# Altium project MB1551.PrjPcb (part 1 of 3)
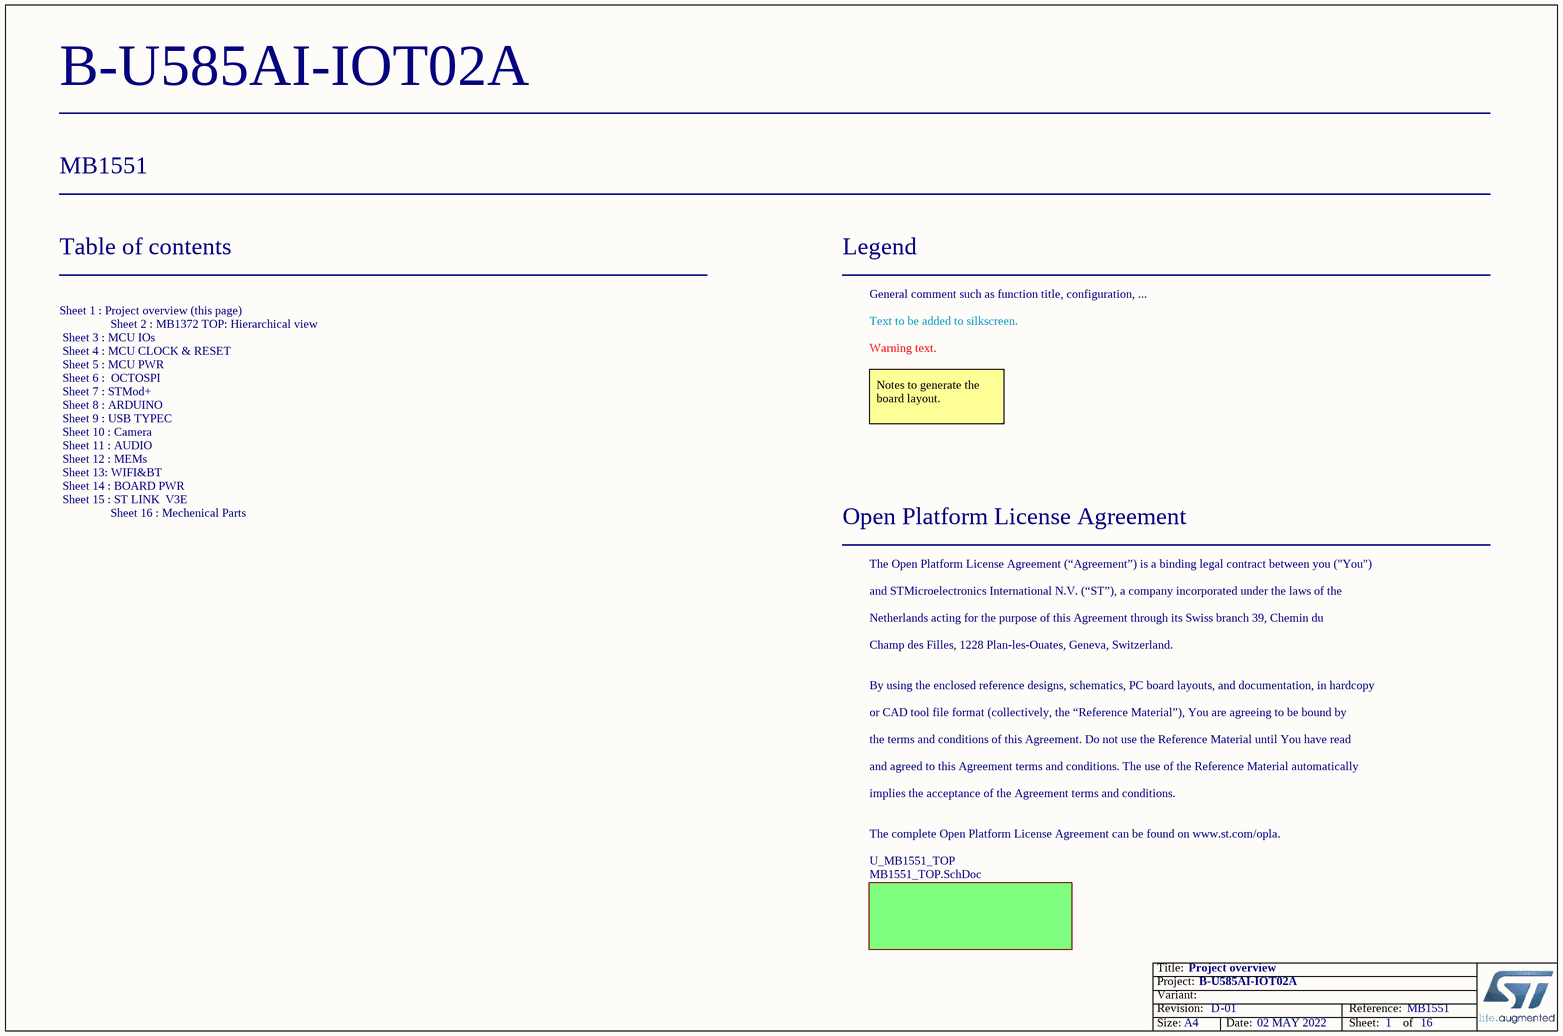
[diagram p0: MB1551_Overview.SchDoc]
Board_Reference: MB1551; Board_PCB_Revision: D; Board_Name: B-U585AI-IOT02A; Board_Document_Date: 02 MAY 2022; Board_Assembly_Revision: 01
16 sheets, 325 parts. Net scope: flat (ports and power ports of the same name join across sheets).
Board file: MB1551.PcbDoc
Sheets:
  MB1551_Overview.SchDoc
    U_MB1551_TOP = MB1551_TOP.SchDoc
      U_ARDUINO = ARDUINO.SchDoc
      U_AUDIO = AUDIO.SchDoc
      U_BOARD_PWR = BOARD_PWR.SchDoc
      U_Camera = Camera.SchDoc
      U_MCU_CLOCK_&_RESET = MCU_CLOCK_&_RESET.SchDoc
      U_MCU_IO = MCU_IO.SchDoc
      U_MCU_PWR = MCU_PWR.SchDoc
      U_Mechanical_Parts = Mechanical_Parts.SchDoc
      U_MEMs = MEMs.SchDoc
      U_OCTOSPI = OCTOSPI.SchDoc
      U_STMod+ = STMod+.SchDoc
      U_ST_LINK_V3E = ST_LINK_V3E.SchDoc
      U_WIFI&BT = WIFI&BT.SchDoc
      U_USB_TYPEC = USB_TYPEC.SchDoc

## Sheet MB1551_Overview.SchDoc: Project overview
size A4; Date: Not used; ApprovedBy: Not used; CheckedBy: Not used; Author: Not used; CompanyName: STMicroelectronics; DrawnBy: Not used; Engineer: Not used; Organization: Not used; Address1: Not used; Address2: Not used; Address3: Not used; Address4: Not used; DocumentNumber: 1; Revision: Not used; SheetNumber: 1; SheetTotal: 16

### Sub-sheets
U_MB1551_TOP = MB1551_TOP.SchDoc: no entries

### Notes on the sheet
- Table of contents
- Legend
- General comment such as function title, configuration, ...
- Text to be added to silkscreen.
- Warning text.
- Notes to generate the board layout.
- Open Platform License Agreement
- The Open Platform License Agreement (“Agreement”) is a binding legal contract between you ("You")
- Sheet 1 : Project overview (this page)
  Sheet 2 : MB1372 TOP: Hierarchical view
  Sheet 3 : MCU IOs
  Sheet 4 : MCU CLOCK & RESET
  Sheet 5 : MCU PWR
  Sheet 6 :  OCTOSPI
  Sheet 7 : STMod+
  Sheet 8 : ARDUINO
  Sheet 9 : USB TYPEC
  Sheet 10 : Camera
  Sheet 11 : AUDIO
  Sheet 12 : MEMs
  Sheet 13: WIFI&BT
  Sheet 14 : BOARD PWR
  Sheet 15 : ST LINK  V3E
  Sheet 16 : Mechenical Parts
- and STMicroelectronics International N.V. (“ST”), a company incorporated under the laws of the
- Netherlands acting for the purpose of this Agreement through its Swiss branch 39, Chemin du
- Champ des Filles, 1228 Plan-les-Ouates, Geneva, Switzerland.
- By using the enclosed reference designs, schematics, PC board layouts, and documentation, in hardcopy
- or CAD tool file format (collectively, the “Reference Material”), You are agreeing to be bound by
- the terms and conditions of this Agreement. Do not use the Reference Material until You have read
- and agreed to this Agreement terms and conditions. The use of the Reference Material automatically
- implies the acceptance of the Agreement terms and conditions.
- The complete Open Platform License Agreement can be found on www.st.com/opla.

## Sheet MB1551_TOP.SchDoc: TOP: Hierarchical view
size A3; Date: Not used; ApprovedBy: Not used; CheckedBy: Not used; Author: Not used; CompanyName: STMicroelectronics; DrawnBy: Not used; Engineer: Not used; Organization: Not used; Address1: Not used; Address2: Not used; Address3: Not used; Address4: Not used; DocumentNumber: 2; Revision: Not used; SheetNumber: 2; SheetTotal: 16
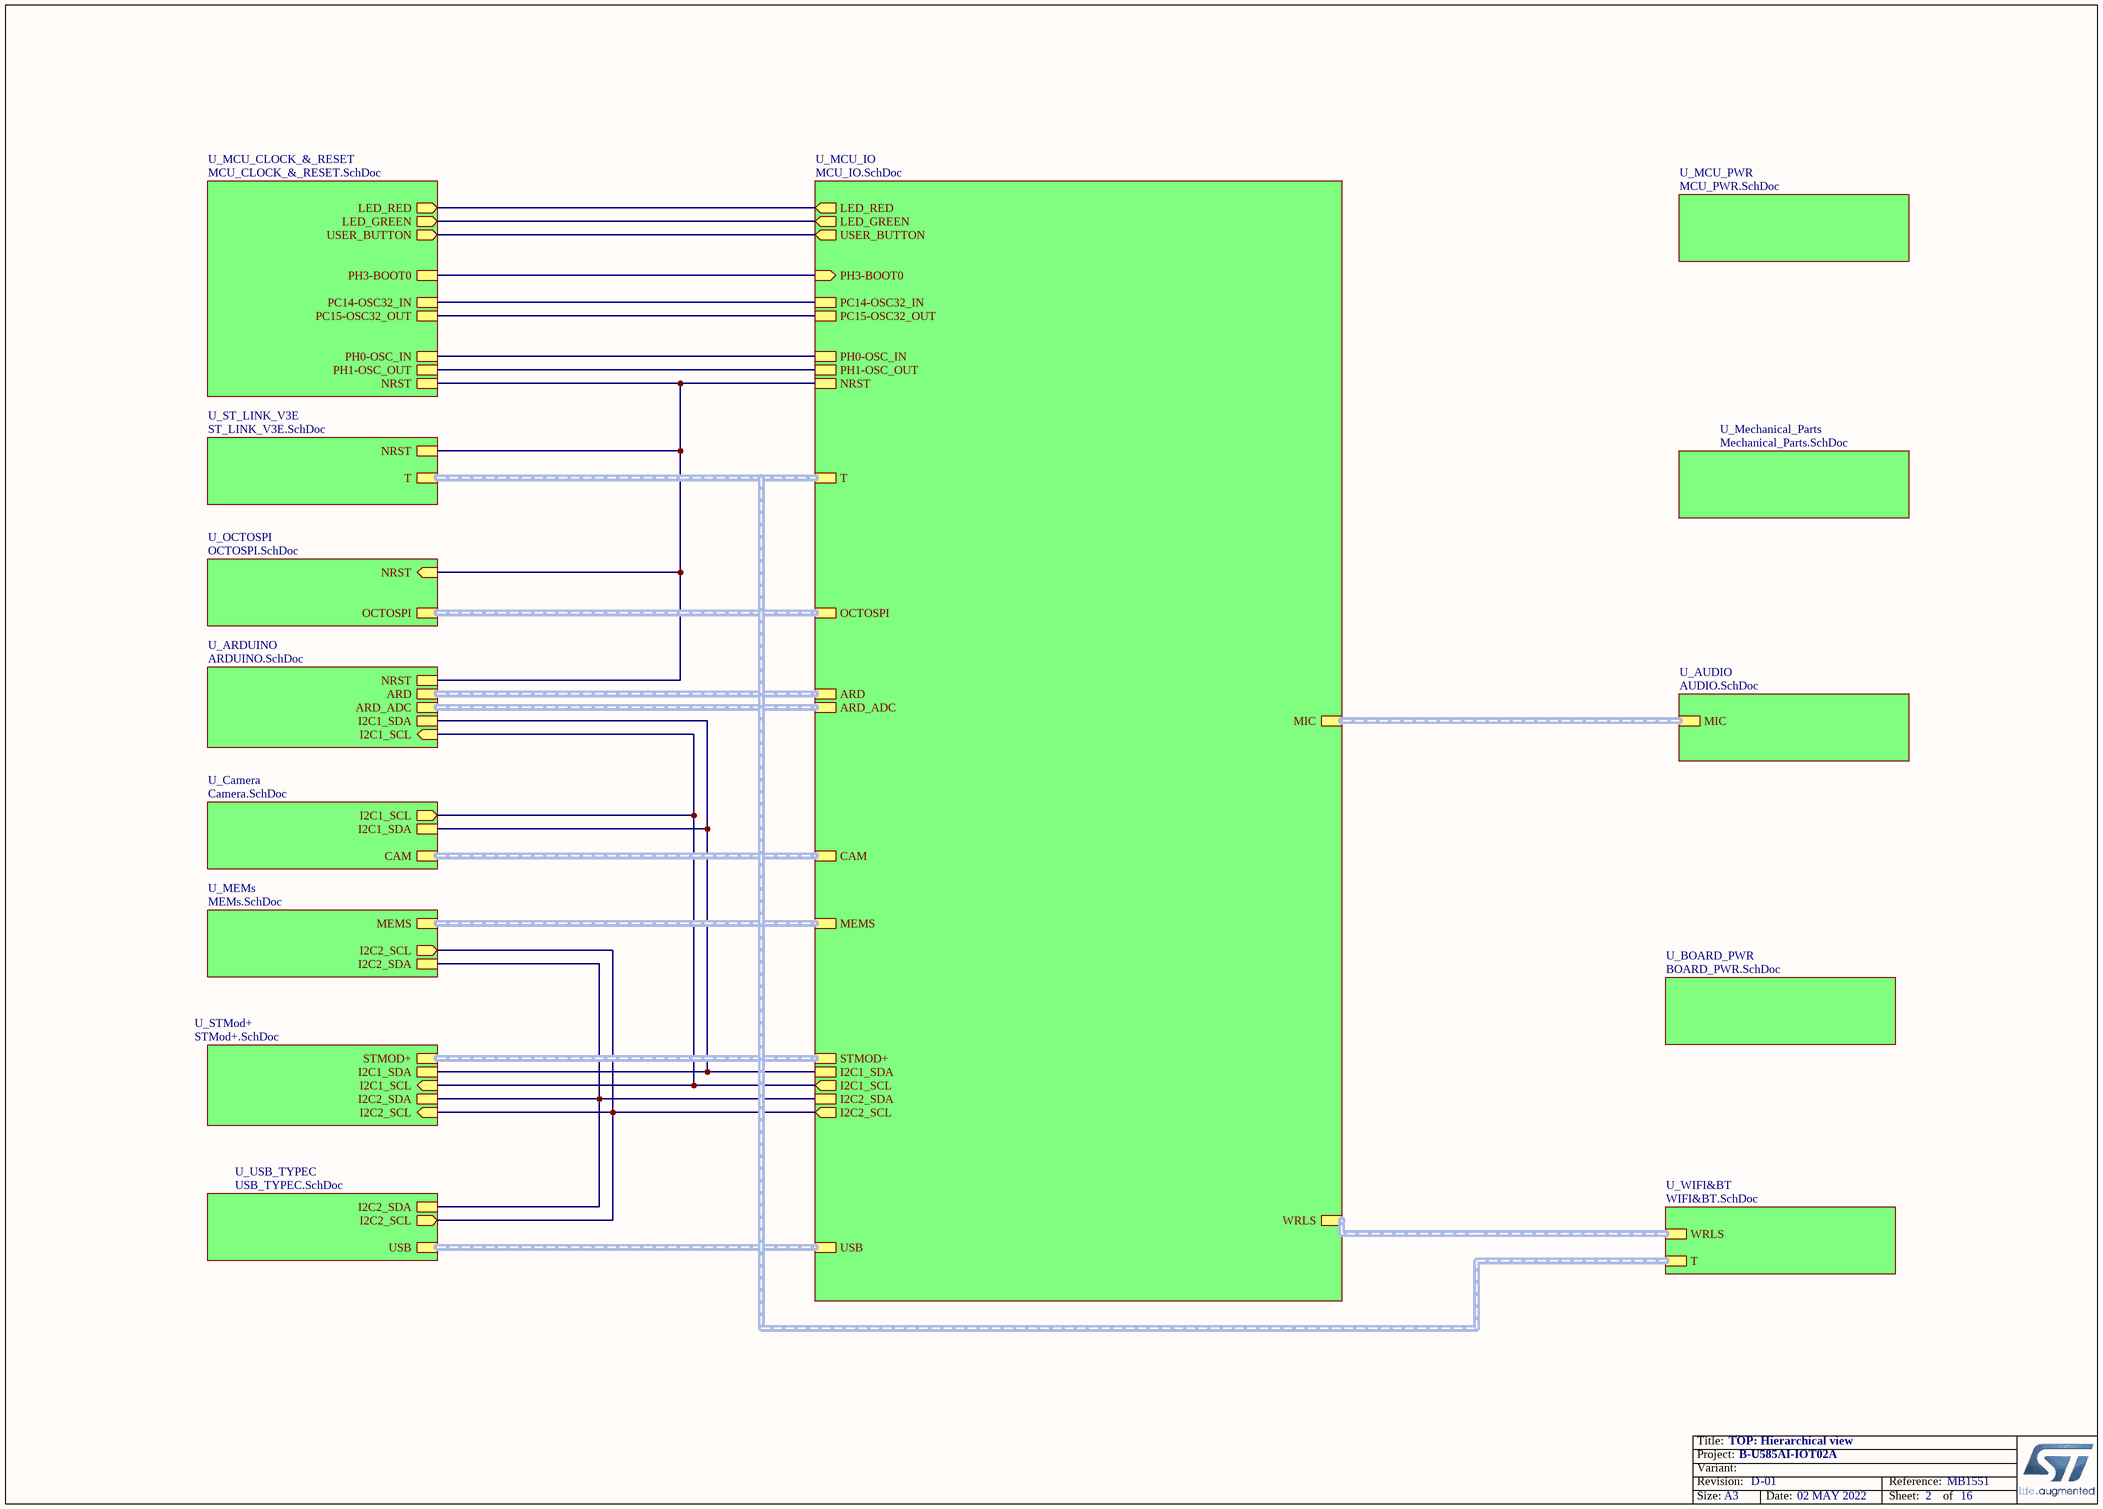
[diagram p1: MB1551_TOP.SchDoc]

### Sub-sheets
U_ARDUINO = ARDUINO.SchDoc: NRST, I2C1_SDA, I2C1_SCL (in), ARD_ADC (harness ARD_ADC), ARD (harness ARD)
U_AUDIO = AUDIO.SchDoc: MIC (harness MIC)
U_BOARD_PWR = BOARD_PWR.SchDoc: no entries
U_Camera = Camera.SchDoc: I2C1_SCL (out), I2C1_SDA, CAM (harness CAM)
U_MCU_CLOCK_&_RESET = MCU_CLOCK_&_RESET.SchDoc: NRST, PH3-BOOT0, PC14-OSC32_IN, PC15-OSC32_OUT, LED_RED (out), LED_GREEN (out), PH0-OSC_IN, PH1-OSC_OUT, USER_BUTTON (out)
U_MCU_IO = MCU_IO.SchDoc: PH3-BOOT0 (in), NRST, PH0-OSC_IN, PH1-OSC_OUT, PC14-OSC32_IN, PC15-OSC32_OUT, LED_RED (out), LED_GREEN (out), USER_BUTTON (out), OCTOSPI (harness OCTOSPI), STMOD+ (harness STMOD+), ARD_ADC (harness ARD_ADC), ARD (harness ARD), USB (harness USB), CAM (harness CAM), MIC (harness MIC), MEMS (harness Mems), WRLS (harness WRLS), T (harness T), I2C1_SDA, I2C1_SCL (out), I2C2_SDA, I2C2_SCL (out)
U_MCU_PWR = MCU_PWR.SchDoc: no entries
U_Mechanical_Parts = Mechanical_Parts.SchDoc: no entries
U_MEMs = MEMs.SchDoc: I2C2_SDA, I2C2_SCL (out), MEMS (harness Mems)
U_OCTOSPI = OCTOSPI.SchDoc: NRST (in), OCTOSPI (harness OCTOSPI)
U_ST_LINK_V3E = ST_LINK_V3E.SchDoc: NRST, T (harness T)
U_STMod+ = STMod+.SchDoc: STMOD+ (harness STMOD+), I2C1_SDA, I2C1_SCL (in), I2C2_SDA, I2C2_SCL (in)
U_USB_TYPEC = USB_TYPEC.SchDoc: USB (harness USB), I2C2_SDA, I2C2_SCL (out)
U_WIFI&BT = WIFI&BT.SchDoc: WRLS (harness WRLS), T (harness T)

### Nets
(unnamed): sheet U_ARDUINO/NRST, sheet U_MCU_CLOCK_&_RESET/NRST, sheet U_MCU_IO/NRST, sheet U_OCTOSPI/NRST, sheet U_ST_LINK_V3E/NRST
(unnamed): sheet U_ARDUINO/I2C1_SDA, sheet U_Camera/I2C1_SDA, sheet U_MCU_IO/I2C1_SDA, sheet U_STMod+/I2C1_SDA  [a separate net that carries the same name]
(unnamed): sheet U_ARDUINO/I2C1_SCL, sheet U_Camera/I2C1_SCL, sheet U_MCU_IO/I2C1_SCL, sheet U_STMod+/I2C1_SCL  [a separate net that carries the same name]
(unnamed): sheet U_MCU_CLOCK_&_RESET/PH3-BOOT0, sheet U_MCU_IO/PH3-BOOT0  [a separate net that carries the same name]
(unnamed): sheet U_MCU_CLOCK_&_RESET/PC14-OSC32_IN, sheet U_MCU_IO/PC14-OSC32_IN  [a separate net that carries the same name]
(unnamed): sheet U_MCU_CLOCK_&_RESET/PC15-OSC32_OUT, sheet U_MCU_IO/PC15-OSC32_OUT  [a separate net that carries the same name]
(unnamed): sheet U_MCU_CLOCK_&_RESET/LED_RED, sheet U_MCU_IO/LED_RED  [a separate net that carries the same name]
(unnamed): sheet U_MCU_CLOCK_&_RESET/LED_GREEN, sheet U_MCU_IO/LED_GREEN  [a separate net that carries the same name]
(unnamed): sheet U_MCU_CLOCK_&_RESET/PH0-OSC_IN, sheet U_MCU_IO/PH0-OSC_IN  [a separate net that carries the same name]
(unnamed): sheet U_MCU_CLOCK_&_RESET/PH1-OSC_OUT, sheet U_MCU_IO/PH1-OSC_OUT  [a separate net that carries the same name]
(unnamed): sheet U_MCU_CLOCK_&_RESET/USER_BUTTON, sheet U_MCU_IO/USER_BUTTON  [a separate net that carries the same name]
(unnamed): sheet U_MCU_IO/I2C2_SDA, sheet U_MEMs/I2C2_SDA, sheet U_STMod+/I2C2_SDA, sheet U_USB_TYPEC/I2C2_SDA  [a separate net that carries the same name]
(unnamed): sheet U_MCU_IO/I2C2_SCL, sheet U_MEMs/I2C2_SCL, sheet U_STMod+/I2C2_SCL, sheet U_USB_TYPEC/I2C2_SCL  [a separate net that carries the same name]

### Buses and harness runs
harness sheet U_ARDUINO/ARD = sheet U_MCU_IO/ARD
harness sheet U_ARDUINO/ARD_ADC = sheet U_MCU_IO/ARD_ADC
harness sheet U_AUDIO/MIC = sheet U_MCU_IO/MIC
harness sheet U_Camera/CAM = sheet U_MCU_IO/CAM
harness sheet U_MCU_IO/MEMS = sheet U_MEMs/MEMS
harness sheet U_MCU_IO/OCTOSPI = sheet U_OCTOSPI/OCTOSPI
harness sheet U_MCU_IO/STMOD+ = sheet U_STMod+/STMOD+
harness sheet U_MCU_IO/T = sheet U_ST_LINK_V3E/T = sheet U_WIFI&BT/T
harness sheet U_MCU_IO/USB = sheet U_USB_TYPEC/USB
harness sheet U_MCU_IO/WRLS = sheet U_WIFI&BT/WRLS

## Sheet ARDUINO.SchDoc: ARDUINO
size A4; Date: Not used; ApprovedBy: Not used; CheckedBy: Not used; Author: Not used; CompanyName: STMicroelectronics; DrawnBy: Not used; Engineer: Not used; Organization: Not used; Address1: Not used; Address2: Not used; Address3: Not used; Address4: Not used; DocumentNumber: 8; Revision: Not used; SheetNumber: 8; SheetTotal: 16
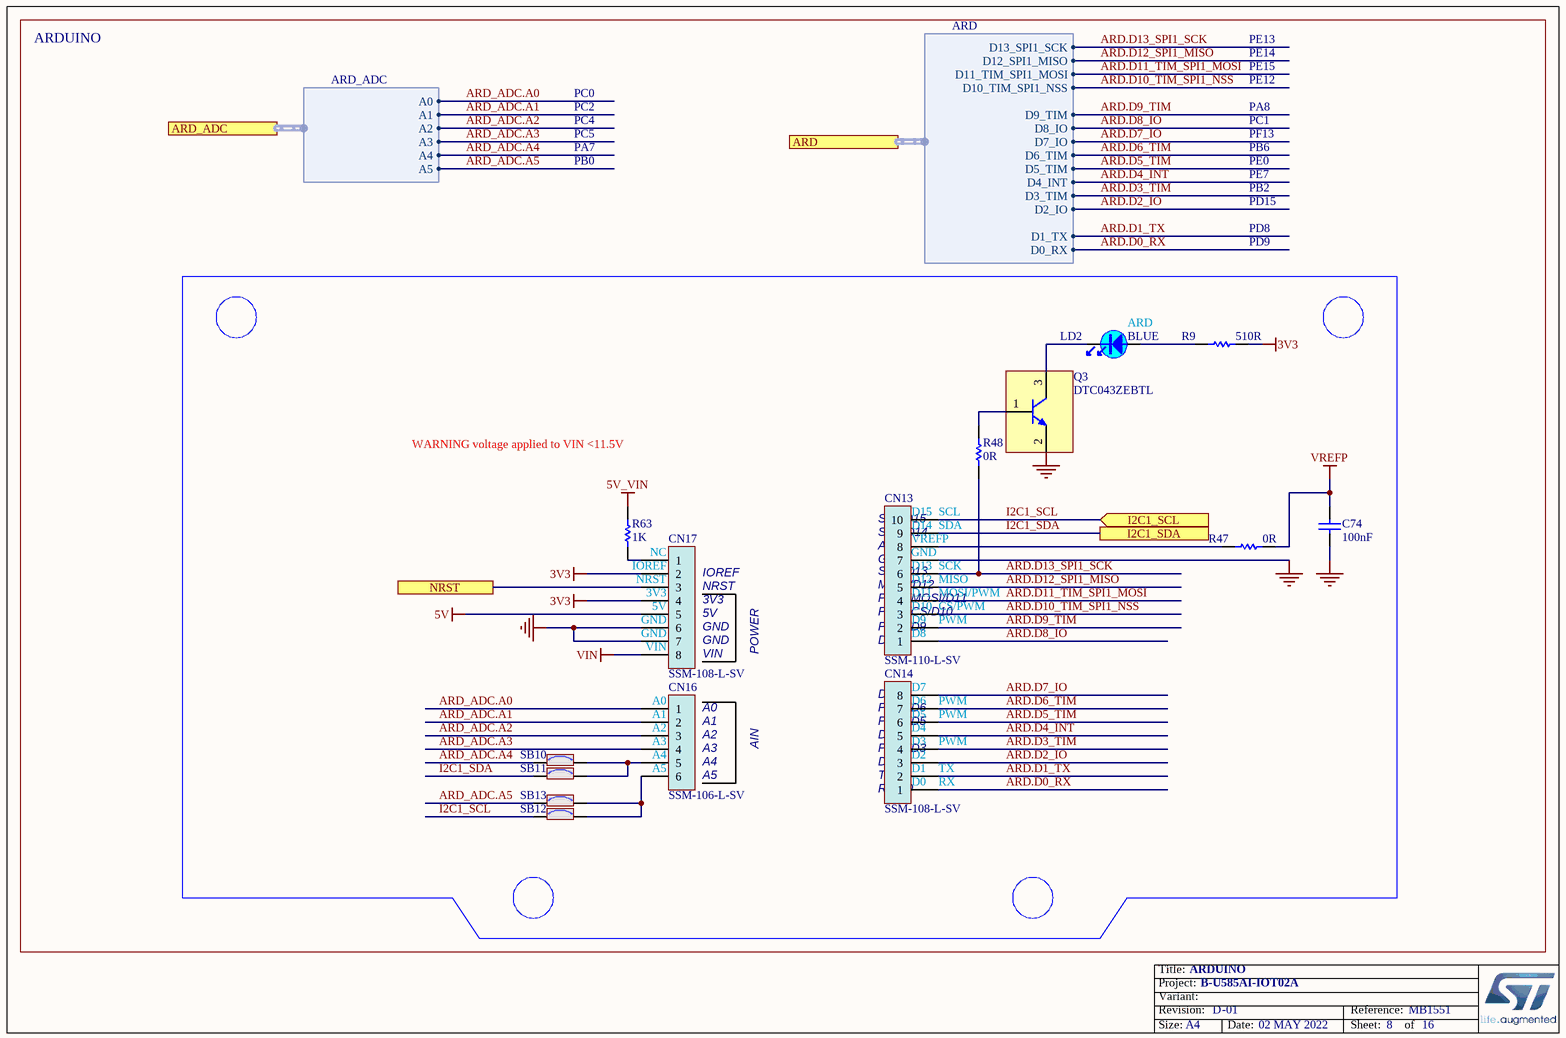
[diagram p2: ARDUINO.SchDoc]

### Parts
C74  value 100nF  [C0402]
CN13  value SSM-110-L-SV  [CON_SAMTEC_SSM-110-L-SV]  (hidden comment: Socket 10x1)
CN14  value SSM-108-L-SV  [CON_SAMTEC_SSM-108-L-SV]  (hidden comment: Socket 8x1)
CN16  value SSM-106-L-SV  [CON_SAMTEC_SSM-106-L-SV]  (hidden comment: Socket 6x1)
CN17  value SSM-108-L-SV  [CON_SAMTEC_SSM-108-L-SV]  (hidden comment: Socket 8x1)
LD2  value BLUE  [LED_0603_SMD-B_BLUE_H0P4]  (hidden comment: ​reference from jiubaba)
Q3  DTC043ZEBTL  [NPN_SOT416-FL_EMT3F_1616_SC89]
R9  value 510R  [R0402]  (hidden comment: Resistor)
R47  value 0R  [R0402]
R48  value 0R  [R0402]
R63  value 1K  [R0402]  (hidden comment: Resistor)
SB10  (no value)  [SOLDER-BRIDGE_R0603-0R]
SB11  (no value)  [SOLDER-BRIDGE_R0603-0R]
SB12  (no value)  [SOLDER-BRIDGE_R0603-0R]
SB13  (no value)  [SOLDER-BRIDGE_R0603-0R]

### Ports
ARD (harness ARD), ARD_ADC (harness ARD_ADC), I2C1_SCL (in), I2C1_SDA, NRST

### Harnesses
ARD: D0_RX, D1_TX, D2_IO, D3_TIM, D4_INT, D5_TIM, D6_TIM, D7_IO, D8_IO, D9_TIM, D10_TIM_SPI1_NSS, D11_TIM_SPI1_MOSI, D12_SPI1_MISO, D13_SPI1_SCK
ARD_ADC: A0, A1, A2, A3, A4, A5

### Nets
3V3: CN17.2 CN17.4 R9.1
5V: CN17.5
5V_VIN: R63.2
GND: C74.2 CN13.7 CN17.6 CN17.7 Q3.2(E)
VIN: CN17.8
VREFP: C74.1 R47.2
ARD.D0_RX: CN14.1 ; port ARD.D0_RX
ARD.D1_TX: CN14.2 ; port ARD.D1_TX
ARD.D2_IO: CN14.3 ; port ARD.D2_IO
ARD.D3_TIM: CN14.4 ; port ARD.D3_TIM
ARD.D4_INT: CN14.5 ; port ARD.D4_INT
ARD.D5_TIM: CN14.6 ; port ARD.D5_TIM
ARD.D6_TIM: CN14.7 ; port ARD.D6_TIM
ARD.D7_IO: CN14.8 ; port ARD.D7_IO
ARD.D8_IO: CN13.1 ; port ARD.D8_IO
ARD.D9_TIM: CN13.2 ; port ARD.D9_TIM
ARD.D10_TIM_SPI1_NSS: CN13.3 ; port ARD.D10_TIM_SPI1_NSS
ARD.D11_TIM_SPI1_MOSI: CN13.4 ; port ARD.D11_TIM_SPI1_MOSI
ARD.D12_SPI1_MISO: CN13.5 ; port ARD.D12_SPI1_MISO
ARD.D13_SPI1_SCK: CN13.6 R48.1 ; port ARD.D13_SPI1_SCK
ARD_ADC.A0: CN16.1 ; port ARD_ADC.A0
ARD_ADC.A1: CN16.2 ; port ARD_ADC.A1
ARD_ADC.A2: CN16.3 ; port ARD_ADC.A2
ARD_ADC.A3: CN16.4 ; port ARD_ADC.A3
ARD_ADC.A4: SB10.1 ; port ARD_ADC.A4
ARD_ADC.A5: SB13.1 ; port ARD_ADC.A5
I2C1_SCL: CN13.10 SB12.1 ; port I2C1_SCL
I2C1_SDA: CN13.9 SB11.1 ; port I2C1_SDA
NRST: CN17.3 ; port NRST
NetCN13_8: CN13.8 R47.1
NetCN16_5: CN16.5 SB10.2 SB11.2
NetCN16_6: CN16.6 SB12.2 SB13.2
NetCN17_1: CN17.1 R63.1
NetLD2_1: LD2.1 R9.2
NetLD2_2: LD2.2 Q3.3(C)
NetQ3_1: Q3.1(B) R48.2

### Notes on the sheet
- ARDUINO
- PE13
- PC2
- PC0
- PA8
- PE15
- PE12
- PE14
- PC5
- PA7
- PC4
- PB0
- PE0
- PB6
- PE7
- PC1
- PF13
- PD8
- PD9
- PB2
- PD15
- (near LD2) ARD
- WARNING voltage applied to VIN <11.5V
- (near CN13) SCL/D15
- (near CN13) D15
- (near CN13) SCL
- (near CN17) NC
- (near CN17) IOREF
- (near CN17) NRST
- (near CN13) SDA/D14
- (near CN13) SCK/D13
- (near CN13) MISO/D12
- (near CN13) AVDD
- (near CN13) GND
- (near CN13) VREFP
- (near CN13) D12
- (near CN13) D13
- (near CN13) D14
- (near CN13) SDA
- (near CN13) SCK
- (near CN13) MISO
- (near CN17) 3V3
- (near CN17) 5V
- (near CN17) GND
- (near CN17) VIN
- POWER
- (near CN13) D8
- (near CN13) PWM/D9
- (near CN13) PWM/CS/D10
- (near CN13) PWM/MOSI/D11
- (near CN13) D9
- (near CN13) D10
- (near CN13) D11
- (near CN13) MOSI/PWM
- (near CN13) CS/PWM
- (near CN13) PWM
- (near CN16) A0
- (near CN16) A1
- (near CN14) PWM/D6
- (near CN14) D7
- (near CN14) D6
- (near CN14) D5
- (near CN14) PWM
- (near CN16) A2
- (near CN16) A3
- (near CN16) A4
- (near CN16) A5
- AIN
- (near CN14) RX/D0
- (near CN14) TX/D1
- (near CN14) D2
- (near CN14) D4
- (near CN14) PWM/D3
- (near CN14) PWM/D5
- (near CN14) D3
- (near CN14) D1
- (near CN14) D0
- (near CN14) TX
- (near CN14) RX

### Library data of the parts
C74 = MCD-00006: Capacitor,100nF,16V,X7R,10%,0402; Manufacturer_Part_Number: CC0402KRX7R7BB104; Manufacturer: YAGEO; Provided_By: Subcon; Initial_Board_Reference: mb1274
CN13 = MCD-02342: Socket, 10x1, 2.54mm, VR, SMT, Height 7.37mm; Part_Type: Connector; Part_Preference: Recommended; Manufacturer: SAMTEC; Order_Code_RS: 765-5420
CN14 CN17 = MCD-02345: Socket, 8x1, 2.54mm, VR, SMT, Height 7.37mm; Part_Type: Connector; Part_Preference: Recommended; Manufacturer: SAMTEC; Order_Code_RS: 765-5411
CN16 = MCD-02346: Socket, 6x1, 2.54mm, VR, SMT, Height 7.37mm; Part_Type: Connector; Part_Preference: Recommended; Manufacturer: SAMTEC; Order_Code_RS: 765-5408
LD2 = MCD-01131: LED Blue, 0603 SMD, Forward Voltage Min=2,8V, Max=3,1V; Part_Type: Display; Manufacturer_Part_Number: 19-217-BHC-ZL1M2RY-3T; Manufacturer: EVERLIGHT; Provided_By: Subcon; Initial_Board_Reference: MB1272
Q3 = MCD-00280: Buffer transistor; Part_Type: IC; Manufacturer: ROHM; Provided_By: Subcon; Initial_Board_Reference: MB1329
R9 = MCD-00064: Resistor,510R,0402,1%,1/16W; Manufacturer_Part_Number: RC0402FR-07510RL; Manufacturer: YAGEO; Provided_By: Subcon; Initial_Board_Reference: MB1274
R47 R48 = MCD-00052: Resistor,0R,0402,5%,1/16W; Manufacturer_Part_Number: RC0402JR-070RL; Manufacturer: YAGEO; Provided_By: Subcon; Initial_Board_Reference: mb1274
R63 = MCD-00061: Resistor,1K,0402,1%,1/16W; Manufacturer_Part_Number: RC0402FR-071KL; Manufacturer: YAGEO; Provided_By: Subcon; Initial_Board_Reference: mb1274
SB10-SB13 = MCD-00071: Solder Bridge ON; Part_Type: Mechanical; Provided_By: Subcon; Initial_Board_Reference: mb1274

## Sheet AUDIO.SchDoc: AUDIO
size A4; Date: Not used; ApprovedBy: Not used; CheckedBy: Not used; Author: Not used; CompanyName: STMicroelectronics; DrawnBy: Not used; Engineer: Not used; Organization: Not used; Address1: Not used; Address2: Not used; Address3: Not used; Address4: Not used; DocumentNumber: 11; Revision: Not used; SheetNumber: 11; SheetTotal: 16
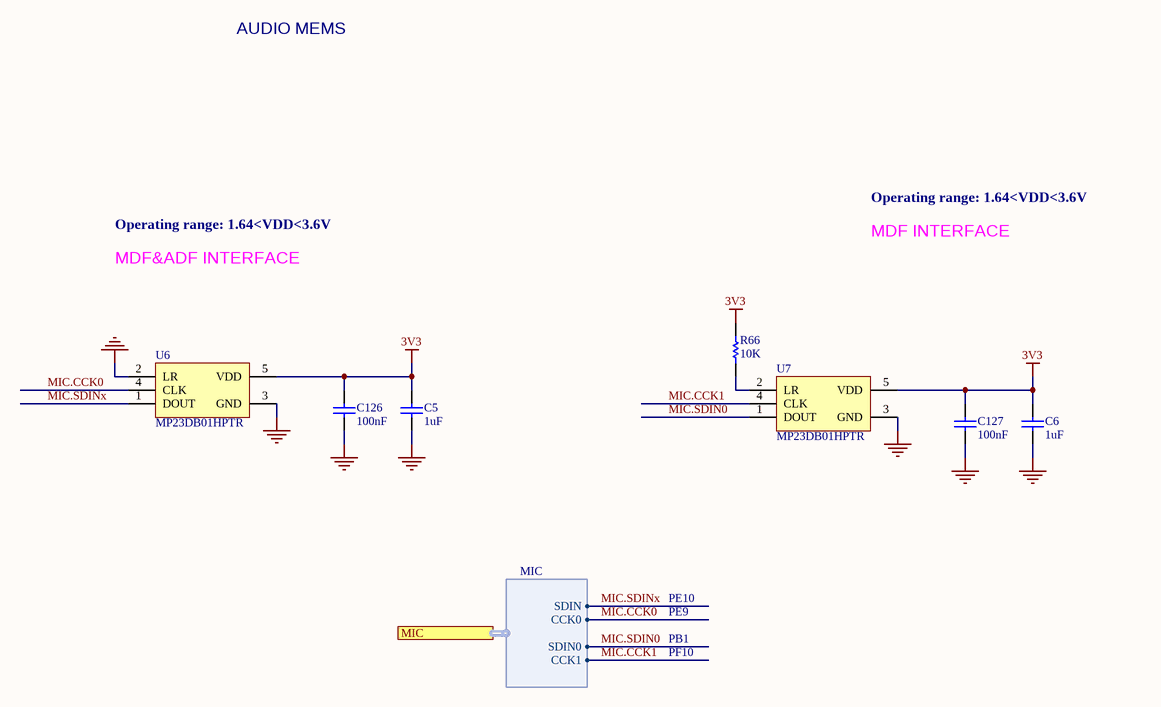
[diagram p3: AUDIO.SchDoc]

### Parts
C5  value 1uF  [C0603]
C6  value 1uF  [C0603]
C126  value 100nF  [C0402]
C127  value 100nF  [C0402]
R66  value 10K  [R0402]  (hidden comment: Resistor)
U6  value MP23DB01HPTR  [MIC_STM_MP23DB01MMTR]  (hidden comment: MP23DB01MMTR)
U7  value MP23DB01HPTR  [MIC_STM_MP23DB01MMTR]  (hidden comment: MP23DB01MMTR)

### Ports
MIC (harness MIC)

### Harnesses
MIC: SDIN, CCK0, SDIN0, CCK1

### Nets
3V3: C5.1 C6.1 C126.1 C127.1 R66.2 U6.5(VDD) U7.5(VDD)
GND: C5.2 C6.2 C126.2 C127.2 U6.2(LR) U6.3(GND) U7.3(GND)
MIC.CCK0: U6.4(CLK) ; port MIC.CCK0
MIC.CCK1: U7.4(CLK) ; port MIC.CCK1
MIC.SDIN0: U7.1(DOUT) ; port MIC.SDIN0
MIC.SDINx: U6.1(DOUT) ; port MIC.SDIN
NetR66_1: R66.1 U7.2(LR)

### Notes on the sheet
- AUDIO MEMS
- Operating range: 1.64<VDD<3.6V
- MDF&ADF INTERFACE
- MDF INTERFACE
- PE9
- PE10
- PB1
- PF10

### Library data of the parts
C5 C6 = MCD-00010: Capacitor, MLCC, 1uF, 16V, X5R, 10%, 0603, T=0,8mm; Manufacturer_Part_Number: CC0603KRX5R7BB105; Manufacturer: YAGEO; Provided_By: Subcon; Initial_Board_Reference: MB1274
C126 C127 = MCD-00006: Capacitor, MLCC, 100nF, 16V, X7R, 10%, 0402, T=0.5mm; Manufacturer_Part_Number: CC0402KRX7R7BB104; Manufacturer: YAGEO; Provided_By: Subcon; Initial_Board_Reference: MB1274
R66 = MCD-00053: Resistor,10K,0402,1%,1/16W; Manufacturer_Part_Number: RC0402FR-0710KL; Manufacturer: YAGEO; BMS_Part_Number: 9131590; ECCN_US: EAR99; ECCN_EU: NEC; Provided_By: SUBCO
U6 U7 = MCD-02122: MEMS sensors , omnidirectionnal digital microphone; Part_Type: IC; Manufacturer: STMICROELECTRONICS; ECCN_US: EAR99; ECCN_EU: NEC; Provided_By: SUBCO with ST control

## Sheet BOARD_PWR.SchDoc: BOARD_PWR
size A4; Date: Not used; ApprovedBy: Not used; CheckedBy: Not used; Author: Not used; CompanyName: STMicroelectronics; DrawnBy: Not used; Engineer: Not used; Organization: Not used; Address1: Not used; Address2: Not used; Address3: Not used; Address4: Not used; DocumentNumber: 14; Revision: Not used; SheetNumber: 14; SheetTotal: 16
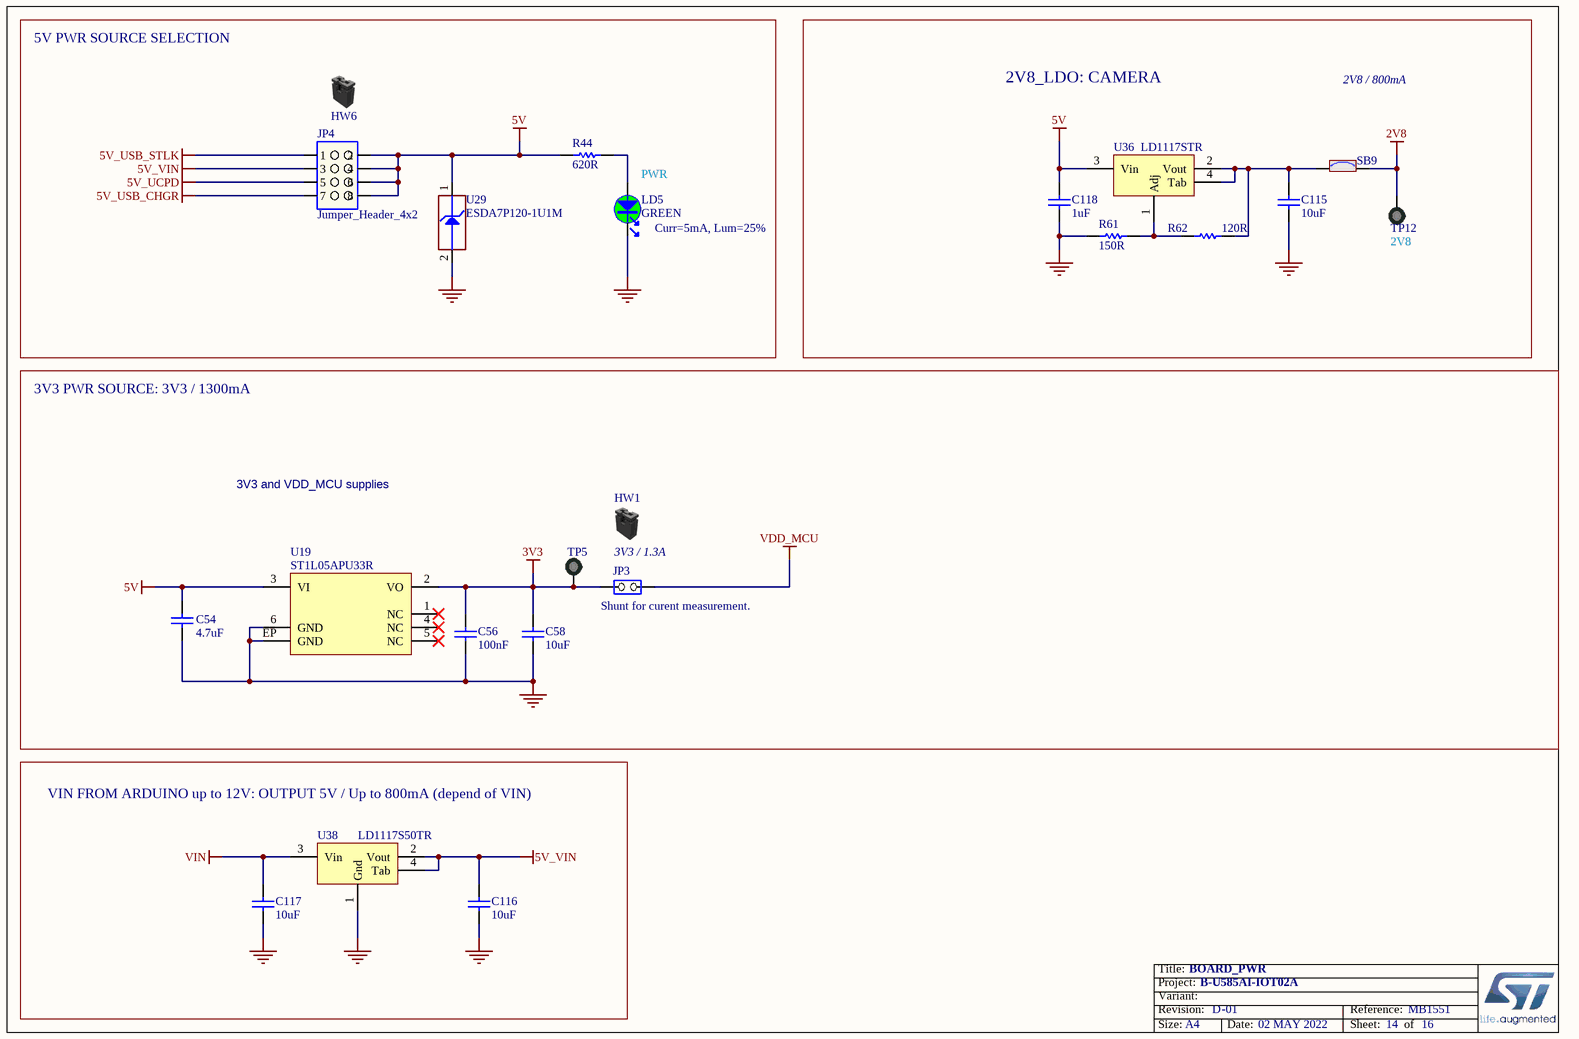
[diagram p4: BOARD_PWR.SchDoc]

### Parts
C54  value 4.7uF  [C0603]
C56  value 100nF  [C0402]
C58  value 10uF  [C0805]  (hidden comment: Capacitor)
C115  value 10uF  [C0402]  (hidden comment: Capacitor)
C116  value 10uF  [C0603]  (hidden comment: Capacitor)
C117  value 10uF  [C0603]  (hidden comment: Capacitor)
C118  value 1uF  [C0603]
HW1  Shunt Black 2.54mm  (value not drawn)  (mechanical)
HW6  (no value)  (mechanical)
JP3  value Shunt for curent measurement.  [CON_SAMTEC_TSW-102-07-G-S]  (hidden comment: Jumper_Header 2x1)
JP4  value Jumper_Header_4x2  [CON_SAMTEC_TSW-104-07-X-D]  (hidden comment: Jumper_Header 4x2)
LD5  value GREEN  [LED_0603_OSRAM_LG-Q396-PS-35_GREEN_1A2K_H0P4]
R44  value 620R  [R0402]
R61  value 150R  [R0603]
R62  value 120R  [R0603]  (hidden comment: Resistor)
SB9  (no value)  [SOLDER-BRIDGE_R0603-0R]
TP5  (no value)  [TP_PTH_1MM_2MM]  (no BOM)
TP12  value 2V8  [TP_PTH_1MM_2MM]  (no BOM)
U19  ST1L05APU33R  [ICC_DFN6-EPAD_3X3_P095]
U29  value ESDA7P120-1U1M  [ESD_QFN1610_2N_1K_2A]  (hidden comment: ESD-TRANSIL)
U36  value LD1117STR  [REG_SOT223-TAB]
U38  LD1117S50TR  [REG_SOT223-TAB]

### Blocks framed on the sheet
5V PWR SOURCE SELECTION: HW6 JP4 LD5 R44 U29
2V8_LDO: CAMERA: C115 C118 R61 R62 SB9 TP12 U36
3V3 PWR SOURCE: 3V3 / 1300mA: C54 C56 C58 HW1 JP3 TP5 U19

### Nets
2V8: SB9.2 TP12.1
3V3: C56.1 C58.2 JP3.2(NO) TP5.1 U19.2(VO)
5V: C54.2 C118.2 JP4.2 JP4.4 JP4.6 JP4.8 R44.2 U19.3(VI) U29.1(IO1) U36.3(Vin)
5V_UCPD: JP4.5
5V_USB_CHGR: JP4.7
5V_USB_STLK: JP4.1
5V_VIN: C116.2 JP4.3 U38.2(Vout) U38.4(Tab)
GND: C54.1 C56.2 C58.1 C115.1 C116.1 C117.1 C118.1 LD5.2 R61.1 U19.6(GND) U19.EP(GND) U29.2(GND) U38.1(Gnd)
VDD_MCU: JP3.1(COMMON)
VIN: C117.2 U38.3(Vin)
NetC115_2: C115.2 R62.2 SB9.1 U36.2(Vout) U36.4(Tab)
NetLD5_1: LD5.1 R44.1
NetR61_2: R61.2 R62.1 U36.1(Adj)

Not connected (* = marked no-connect by the designer): U19 1(NC)* 4(NC)* 5(NC)*

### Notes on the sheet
- 2V8 / 800mA
- (near LD5) PWR
- (near LD5) Curr=5mA, Lum=25%
- 3V3 and VDD_MCU supplies
- 3V3 / 1.3A
- VIN FROM ARDUINO up to 12V: OUTPUT 5V / Up to 800mA (depend of VIN)

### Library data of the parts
C54 = MCD-00009: Capacitor, MLCC, 4.7uF, 16V, X5R, 10%, 0603, T=0.8mm; Manufacturer_Part_Number: CC0603KRX5R7BB475; Manufacturer: YAGEO; ECCN_US: EAR99; ECCN_EU: NEC; Provided_By: SUBCO
C56 = MCD-00006: Capacitor, MLCC, 100nF, 16V, X7R, 10%, 0402, T=0.5mm; Manufacturer_Part_Number: CC0402KRX7R7BB104; Manufacturer: YAGEO; Alternate_Manufacturer_Part_Number: GCM155R71C104KA55D; Alternate_Manufacturer: MURATA; Provided_By: SUBCO; ECCN_US: EAR99; ECCN_EU: NEC
C58 = MCD-00014: Capacitor, MLCC, 10uF, 25V, X5R, 10%, 0805, T=0,85mm; Manufacturer_Part_Number: CC0805KRX5R8BB106; Manufacturer: YAGEO; Provided_By: SUBCO
C115 = MCD-01355: Capacitor, MLCC, 10uF, 4V, X5R, 20%, 0402, T=0,5mm; Manufacturer_Part_Number: GRM155R60G106ME44; Manufacturer: MURATA; ECCN_US: EAR99; ECCN_EU: NEC; Provided_By: Subcon; Initial_Board_Reference: MB1372
C116 C117 = MCD-00099: Capacitor, MLCC, 10uF, 10V, X5R, 10%, 0603, T=0,8mm; Manufacturer_Part_Number: GRM188R61A106KE69D; Manufacturer: MURATA; Provided_By: SUBCO; Initial_Board_Reference: MB1262; Item Type: Item; Path: ws/MCD_ApplicationBoards/Lists/MCDPARTSdatabase
C118 = MCD-00010: as C5 on sheet AUDIO
HW1 = MCD-00043: SHUNT 2.54mm BLACK; Manufacturer_Part_Number: SNT-100-BK-G; Manufacturer: SAMTEC; Part_Type: Mechanical; Provided_By: Subcon; Initial_Board_Reference: MB1274
HW6 = MCD-00043: SHUNT 2.54mm BLACK; Part_Type: Mechanical; Manufacturer_Part_Number: SNT-100-BK-G; Manufacturer: SAMTEC; Provided_By: Subcon; Initial_Board_Reference: MB1274
JP3 = MCD-00045: Header, 2x1, 2,54mm, VR, TH, Height 5.84mm/2.54mm; Part_Type: Connector; Manufacturer_Part_Number: TSW-102-07-x-S; Manufacturer: SAMTEC; Provided_By: Subcon; Initial_Board_Reference: MB1274; Remark: 3D KO: BZ: 40098
JP4 = MCD-00633: Header, 4x2, 2,54mm, VR, TH, Height 5.84mm/2.54mm; Part_Type: Connector; Manufacturer_Part_Number: TSW-104-07-x-D; Manufacturer: SAMTEC; Provided_By: SUBCO
LD5 = MCD-00588: LED Green, 0603 SMD, Forward Voltage Typ=2V, Max=2.5V; Part_Type: Display; Manufacturer_Part_Number: LG Q396-PS-35; Manufacturer: OSRAM OPTO SEMICONDUCTORS; Alternate_Manufacturer_Part_Number: VLMTG1300-GS08; Alternate_Manufacturer: VISHAY SEMICONDUCTOR OPTO DIVISION; Provided_By: Subcon; Initial_Board_Reference: MB1331
R44 = MCD-00499: Resistor,620R,0402,1%,1/16W; Manufacturer_Part_Number: RC0402FR-07620RL; Manufacturer: YAGEO; Provided_By: Subcon
R61 = MCD-00394: Resistor,150,0603,1%,1/10W; Manufacturer_Part_Number: RC0603FR-07150RL; Manufacturer: YAGEO; ECCN_US: EAR99; ECCN_EU: NEC; Provided_By: SUBCO
R62 = MCD-00338: Resistor,120R,0603,1%,1/10W; Manufacturer_Part_Number: RC0603FR-07120RL; Manufacturer: YAGEO; BMS_Part_Number: 9129734; ECCN_US: EAR99; ECCN_EU: NEC; Provided_By: SUBCO
SB9 = MCD-00071: Solder Bridge ON; Part_Type: Mechanical; Provided_By: Subcon; Initial_Board_Reference: MB1274
TP5 TP12 = MCD-01506: Test Point trought hole 1mm/2mm; Part_Type: Mechanical; Initial_Board_Reference: MB1372; Item Type: Item; Path: ws/MCD_ApplicationBoards/Lists/MCDPARTSdatabase
U19 = MCD-01127: IC REG LDO 3.3V 1.3A 6DFN; Manufacturer: STMICROELECTRONICS; BMS_Part_Number: 9176247; Provided_By: SUBCO with ST control
U29 = MCD-01026: High power transient voltage suppressor; Part_Type: Diode; Manufacturer: STMICROELECTRONICS; Provided_By: SUBCO with ST control; Initial_Board_Reference: MB1378; Remark: Footprint moved fromROU lib: DFN105P160X60-2N to global-lib: ESD_QFN1610_2N_1K_2A; Item Type: Item; Path: ws/MCD_ApplicationBoards/Lists/MCDPARTSdatabase
U36 = MCD-00721: LDO Voltage Regulator, Adjustable, 15V in, 1.1V drop, 1.25V to 15V/0.8A out, SOT-223-3; Part_Type: IC; Manufacturer: STMICROELECTRONICS; BMS_Part_Number: 9176132; ECCN_US: EAR99; ECCN_EU: NEC; Provided_By: SUBCO with ST control
U38 = MCD-00088: IC REG LDO 5V 0.8A SOT223; Manufacturer: STMICROELECTRONICS; ECCN_US: EAR99; ECCN_EU: NEC; Provided_By: Subcon; Initial_Board_Reference: MB1274

## Sheet Camera.SchDoc: CAMERA
size A4; Date: Not used; ApprovedBy: Not used; CheckedBy: Not used; Author: Not used; CompanyName: STMicroelectronics; DrawnBy: Not used; Engineer: Not used; Organization: Not used; Address1: Not used; Address2: Not used; Address3: Not used; Address4: Not used; DocumentNumber: 10; Revision: Not used; SheetNumber: 10; SheetTotal: 16
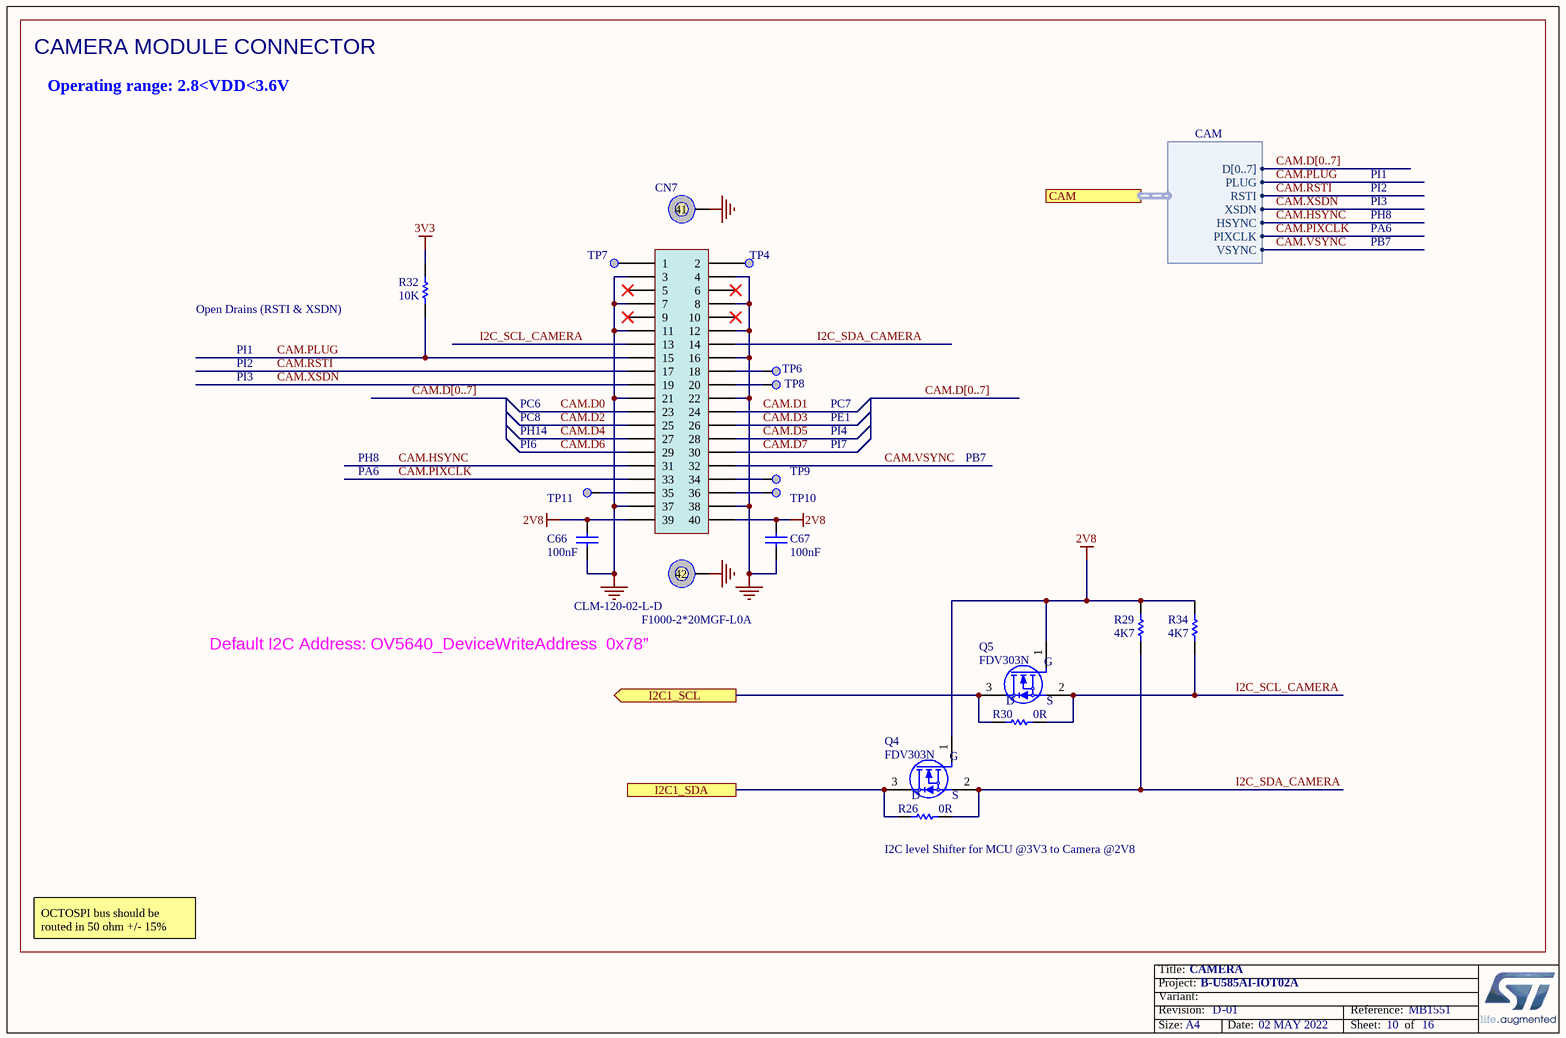
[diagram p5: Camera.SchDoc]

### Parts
C66  value 100nF  [C0402]
C67  value 100nF  [C0402]
CN7  value CLM-120-02-L-D  [CON_SAMTEC_CLM-120-02-L-D_Reverse-to-Camera]
Q4  value FDV303N  [MOS_SOT23]  (hidden comment: BSN20)
Q5  value FDV303N  [MOS_SOT23]  (hidden comment: BSN20)
R26  value 0R  [R0603]  (hidden comment: Resistor)
R29  value 4K7  [R0402]
R30  value 0R  [R0603]  (hidden comment: Resistor)
R32  value 10K  [R0603]
R34  value 4K7  [R0402]
TP4  Test Point  [TP_SMD_1MM]  (value not drawn)  (no BOM)
TP6  Test Point  [TP_SMD_1MM]  (value not drawn)  (no BOM)
TP7  Test Point  [TP_SMD_1MM]  (value not drawn)  (no BOM)
TP8  Test Point  [TP_SMD_1MM]  (value not drawn)  (no BOM)
TP9  Test Point  [TP_SMD_1MM]  (value not drawn)  (no BOM)
TP10  Test Point  [TP_SMD_1MM]  (value not drawn)  (no BOM)
TP11  Test Point  [TP_SMD_1MM]  (value not drawn)  (no BOM)

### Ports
CAM (harness CAM), I2C1_SCL (out), I2C1_SDA

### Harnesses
CAM: D[0..7], PLUG, XSDN, HSYNC, PIXCLK, VSYNC, RSTI

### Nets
2V8: C66.2 C67.2 CN7.39 CN7.40 Q4.1(G) Q5.1(G) R29.2 R34.2
3V3: R32.2
GND: C66.1 C67.1 CN7.3 CN7.4 CN7.7 CN7.8 CN7.11 CN7.12 CN7.16 CN7.21 CN7.22 CN7.37 CN7.38 CN7.41 CN7.42
CAM.D0: CN7.23
CAM.D1: CN7.24
CAM.D2: CN7.25
CAM.D3: CN7.26
CAM.D4: CN7.27
CAM.D5: CN7.28
CAM.D6: CN7.29
CAM.D7: CN7.30
CAM.HSYNC: CN7.31 ; port CAM.HSYNC
CAM.PIXCLK: CN7.33 ; port CAM.PIXCLK
CAM.PLUG: CN7.15 R32.1 ; port CAM.PLUG
CAM.RSTI: CN7.17 ; port CAM.RSTI
CAM.VSYNC: CN7.32 ; port CAM.VSYNC
CAM.XSDN: CN7.19 ; port CAM.XSDN
I2C1_SCL: Q5.3(D) R30.1 ; port I2C1_SCL
I2C1_SDA: Q4.3(D) R26.1 ; port I2C1_SDA
I2C_SCL_CAMERA: CN7.13 Q5.2(S) R30.2 R34.1
I2C_SDA_CAMERA: CN7.14 Q4.2(S) R26.2 R29.1
NetCN7_1: CN7.1 TP7.1
NetCN7_2: CN7.2 TP4.1
NetCN7_18: CN7.18 TP6.1
NetCN7_20: CN7.20 TP8.1
NetCN7_34: CN7.34 TP9.1
NetCN7_35: CN7.35 TP11.1
NetCN7_36: CN7.36 TP10.1

Not connected (* = marked no-connect by the designer): CN7 5* 6* 9* 10*

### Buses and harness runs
bus CAM.D[0..7]

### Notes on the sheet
- CAMERA MODULE CONNECTOR
- Operating range: 2.8<VDD<3.6V
- PI1
- PI2
- PI3
- PH8
- PA6
- PB7
- Open Drains (RSTI & XSDN)
- PC6
- PC8
- PH14
- PI6
- PC7
- PE1
- PI4
- PI7
- Default I2C Address: OV5640_DeviceWriteAddress  0x78”
- (near CN7) F1000-2*20MGF-L0A
- (near R26) I2C level Shifter for MCU @3V3 to Camera @2V8
- OCTOSPI bus should be routed in 50 ohm +/- 15%

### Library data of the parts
C66 C67 = MCD-00006: as C56 on sheet BOARD_PWR
CN7 = MCD-00138: Socket, 20x2, 1.0mm, VR, SMT, Height 2.26mm. Symbol & Footprint dedicated to MB1183 & MB1379 camera modules (not in line with Samtec datasheet); Part_Type: Connector; Provided_By: SUBCO; ECCN_US: EAR99; ECCN_EU: NEC
Q4 Q5 = MCD-01164: N-channel Digital FET; Part_Type: IC; Manufacturer: FAIRCHILD; BMS_Part_Number: 9153036; Provided_By: SUBCO
R26 R30 = MCD-00056: Resistor,0R,0603,5%,1/10W; Manufacturer_Part_Number: RC0603JR-070RL; Manufacturer: YAGEO; Provided_By: SUBCO; ECCN_US: EAR99; ECCN_EU: NEC
R29 R34 = MCD-00065: Resistor,4K7,0402,1%,1/16W; Manufacturer_Part_Number: RC0402FR-074K7L; Manufacturer: YAGEO; Alternate_Manufacturer_Part_Number: RT0402FRE074K7L; Provided_By: SUBCO; ECCN_US: EAR99; ECCN_EU: NEC
R32 = MCD-00220: Resistor,10K,0603,1%,1/10W; Manufacturer_Part_Number: RC0603FR-0710KL; Manufacturer: YAGEO; Provided_By: Subcon; Initial_Board_Reference: MB1319
TP4 TP6-TP11 = MCD-00074: Test Point 1mm; Part_Type: Mechanical

## Sheet MCU_CLOCK_&_RESET.SchDoc: MCU_CLOCK_&_RESET
size A4; Date: Not used; ApprovedBy: Not used; CheckedBy: Not used; Author: Not used; CompanyName: STMicroelectronics; DrawnBy: Not used; Engineer: Not used; Organization: Not used; Address1: Not used; Address2: Not used; Address3: Not used; Address4: Not used; DocumentNumber: 4; Revision: Not used; SheetNumber: 4; SheetTotal: 16
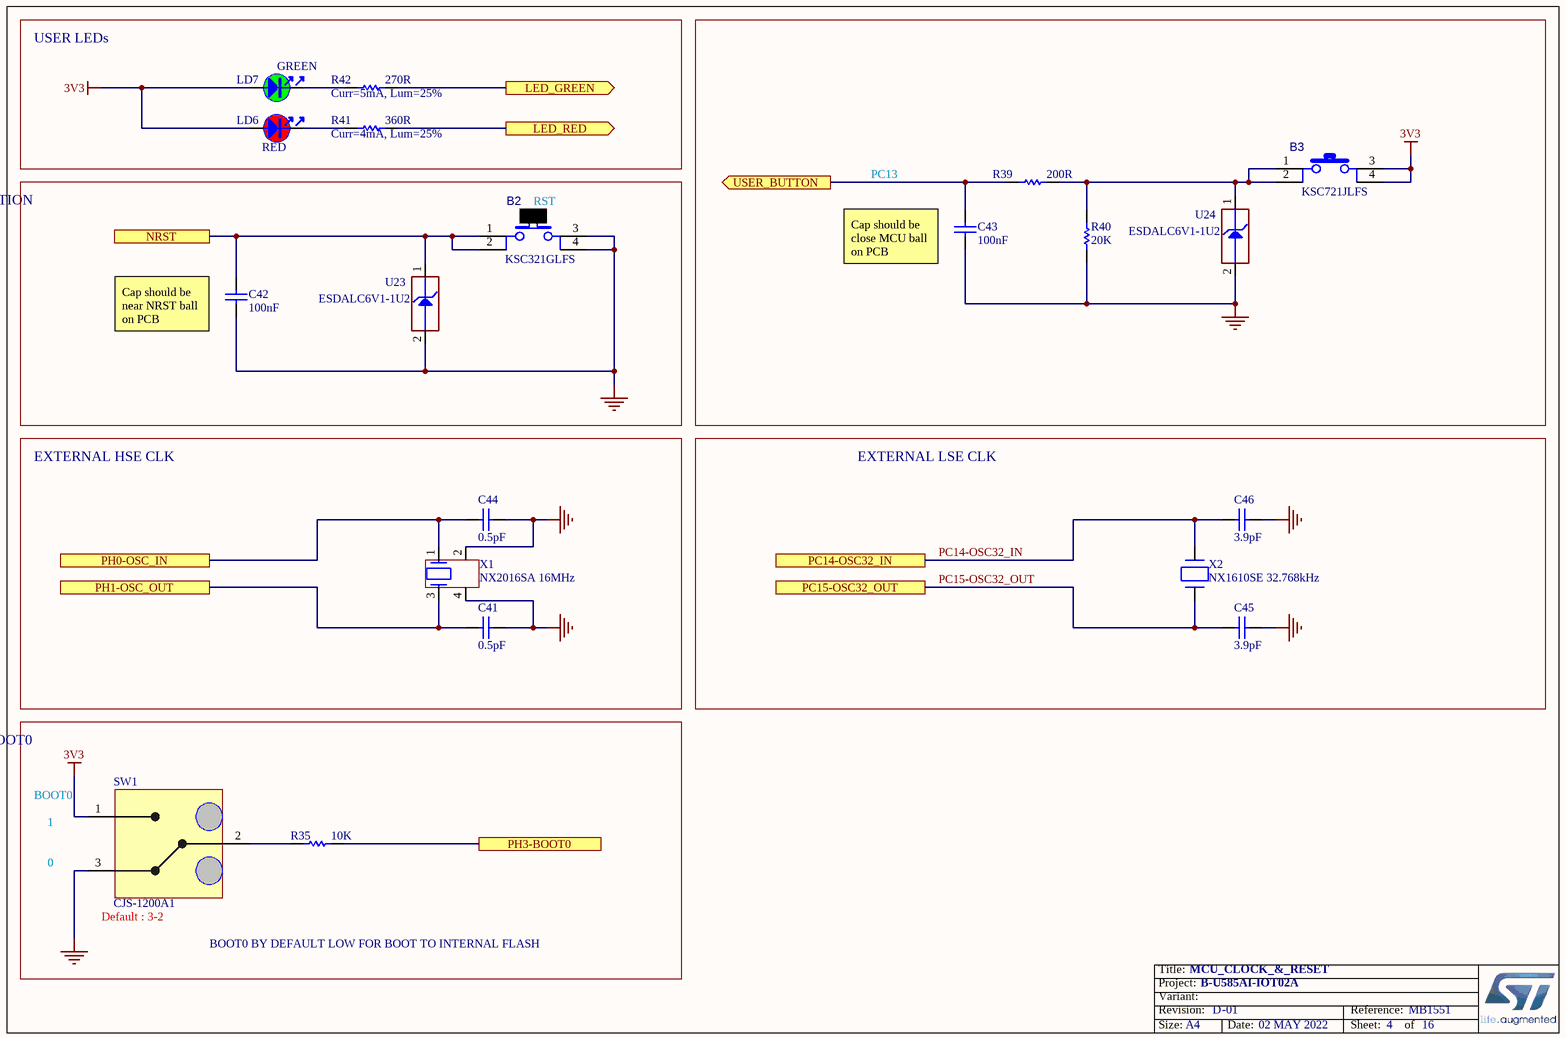
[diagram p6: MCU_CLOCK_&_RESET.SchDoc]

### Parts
B2  value KSC321GLFS  [SWI_C&K_KSC321GLFS_BLACK]  (hidden comment: SW_BLACK_KSC321GLFS)
B3  value KSC721JLFS  [SWI_C&K_KSC721JLFS_BLUE]  (hidden comment: SW_BLUE_KSC721JLFS)
C41  value 0.5pF  [C0402]  (hidden comment: Capacitor)
C42  value 100nF  [C0402]  (hidden comment: Capacitor)
C43  value 100nF  [C0402]
C44  value 0.5pF  [C0402]  (hidden comment: Capacitor)
C45  value 3.9pF  [C0402]  (hidden comment: Capacitor)
C46  value 3.9pF  [C0402]  (hidden comment: Capacitor)
LD6  value RED  [LED_0603_VISHAY_VLMS1300-GS08_RED_1A2K_H0P8]  (hidden comment: LED_red)
LD7  value GREEN  [LED_0603_OSRAM_LG-Q396-PS-35_GREEN_1A2K_H0P4]
R35  value 10K  [R0603]
R39  value 200R  [R0603]
R40  value 20K  [R0603]
R41  value 360R  [R0402]
R42  value 270R  [R0402]
SW1  CJS-1200A1  [SWI_CJS-1200A1]
U23  value ESDALC6V1-1U2  [ESD_ST0201]
U24  value ESDALC6V1-1U2  [ESD_ST0201]
X1  value NX2016SA 16MHz  [CRY_NX2016SA_4P]  (hidden comment: XTAL_4_PINS)
X2  value NX1610SE 32.768kHz  [CRY_NX1610SE_2P]  (hidden comment: XTAL_2_PINS)

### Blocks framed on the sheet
USER LEDs: LD6 LD7 R41 R42
PC13: B3 C43 R39 R40 U24
RESET FUNCTION: B2 C42 U23
EXTERNAL HSE CLK: C41 C44 X1
EXTERNAL LSE CLK: C45 C46 X2
PH3_BOOT0: R35 SW1

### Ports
LED_GREEN (out), LED_RED (out), NRST, PC14-OSC32_IN, PC15-OSC32_OUT, PH0-OSC_IN, PH1-OSC_OUT, PH3-BOOT0, USER_BUTTON (out)

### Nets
3V3: B3.3 B3.4 LD6.1 LD7.1 SW1.1
GND: B2.3 B2.4 C41.2 C42.1 C43.1 C44.2 C45.2 C46.2 R40.1 SW1.3 U23.2(GND) U24.2(GND) X1.2 X1.4
LED_GREEN: R42.2 ; port LED_GREEN
LED_RED: R41.2 ; port LED_RED
NRST: B2.1 B2.2 C42.2 U23.1(IO1) ; port NRST
PC14-OSC32_IN: C46.1 X2.2(X2) ; port PC14-OSC32_IN
PC15-OSC32_OUT: C45.1 X2.1(X1) ; port PC15-OSC32_OUT
PH0-OSC_IN: C44.1 X1.1 ; port PH0-OSC_IN
PH1-OSC_OUT: C41.1 X1.3 ; port PH1-OSC_OUT
PH3-BOOT0: R35.2 ; port PH3-BOOT0
USER_BUTTON: C43.2 R39.1 ; port USER_BUTTON
NetB3_1: B3.1 B3.2 R39.2 R40.2 U24.1(IO1)
NetLD6_2: LD6.2 R41.1
NetLD7_2: LD7.2 R42.1
NetR35_1: R35.1 SW1.2

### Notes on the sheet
- (near R42) Curr=5mA, Lum=25%
- (near R41) Curr=4mA, Lum=25%
- (near B2) RST
- (near C43) Cap should be close MCU ball on PCB
- (near C42) Cap should be near NRST ball on PCB
- (near SW1) BOOT0
- 1
- 0
- (near SW1) Default : 3-2
- BOOT0 BY DEFAULT LOW FOR BOOT TO INTERNAL FLASH

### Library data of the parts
B2 = MCD-00175: Switch HW BLACK High3.5mm 2Newtons; Part_Type: Misc; Manufacturer: C&K; Provided_By: SUBCO; Initial_Board_Reference: MB1274
B3 = MCD-01800: Switch HW BLUE High4.3mm 2.25 Newtons, BEND type; Part_Type: Misc; Manufacturer: C&K; Provided_By: SUBCO
C41 C44 = MCD-02215: Capacitor, MLCC, 0.5pF, 50V, C0G, +-0.1pF, 0402, T=0.5mm; Part_Preference: Recommended; Manufacturer: MURATA; Manufacturer_Part_Number: GJM1555C1HR50BB01D; Order_Code_RS: 723-5111P
C42 = MCD-00006: Capacitor, MLCC, 100nF, 16V, X7R, 10%, 0402, T=0.5mm; Manufacturer_Part_Number: CC0402KRX7R7BB104; Manufacturer: YAGEO; Provided_By: SUBCO; Initial_Board_Reference: MB1274
C43 = MCD-00006: as C56 on sheet BOARD_PWR
C45 C46 = MCD-00556: Capacitor, MLCC, 3.9pF, 50V, NPO, +/-0.25pF, 0402, T=0.5mm; Part_Preference: Recommended; Manufacturer: YAGEO; Manufacturer_Part_Number: CC0402CRNPO9BN3R9; Component_Country_Of_Origin: China
LD6 = MCD-00587: LED Red, 0603 SMD, 2V Forward Voltage; Part_Type: Display; Manufacturer_Part_Number: VLMS1300-GS08; Manufacturer: VISHAY; Alternate_Manufacturer_Part_Number: LS Q976-NR-1; Alternate_Manufacturer: OSRAM OPTO SEMICONDUCTORS; Provided_By: SUBCO; Initial_Board_Reference: MB1331; Item Type: Item; Path: ws/MCD_ApplicationBoards/Lists/MCDPARTSdatabase
LD7 = MCD-00588: as LD5 on sheet BOARD_PWR
R35 = MCD-00220: as R32 on sheet Camera
R39 = MCD-00418: Resistor,200R,0603,1%,1/10W; Manufacturer_Part_Number: RC0603FR-07200RL; Manufacturer: YAGEO; Provided_By: SUBCO; ECCN_US: EAR99; ECCN_EU: NEC
R40 = MCD-00422: Resistor,20K,0603,1%,1/10W; Manufacturer_Part_Number: RC0603FR-0720KL; Manufacturer: YAGEO; Provided_By: Subcon
R41 = MCD-00461: Resistor,360R,0402,1%,1/16W; Manufacturer_Part_Number: RC0402FR-07360RL; Manufacturer: YAGEO; Provided_By: Subcon
R42 = MCD-00441: Resistor,270R,0402,1%,1/16W; Manufacturer_Part_Number: RC0402FR-07270RL; Manufacturer: YAGEO; Provided_By: Subcon
SW1 = MCD-02279: SLIDE SWITCHE (SMD) serie CJS; Part_Preference: Recommended; Part_Type: Misc; Manufacturer: NIDEC Copal
U23 U24 = MCD-00170: ESD protection 6V1; Part_Type: Diode; Manufacturer: STMICROELECTRONICS; ECCN_US: EAR99; ECCN_EU: NEC; Provided_By: Subcon; Initial_Board_Reference: MB1274
X1 = MCD-01476: Crystal 16 MHz, 8pF, -+20 PPM, R=200Ω, SMD; Part_Type: Crystal_Osc; Manufacturer_Part_Number: NX2016SA 16 MHz EXS00A-CS07826; Manufacturer: NDK; Provided_By: ST; Initial_Board_Reference: MB1373; Item Type: Item; Path: ws/MCD_ApplicationBoards/Lists/MCDPARTSdatabase
X2 = MCD-02291: Crystal 32.768kHz, 9pF, -+20ppm, 70Kohm max, SMD; Part_Type: Crystal_Osc; Part_Preference: Recommended; Manufacturer: NDK; Manufacturer_Part_Number: NX1610SE 32.768KHz EXS00A-MU01499

## Sheet MCU_IO.SchDoc: MCU IOs
size A3; Date: Not used; ApprovedBy: Not used; CheckedBy: Not used; Author: Not used; CompanyName: STMicroelectronics; DrawnBy: Not used; Engineer: Not used; Organization: Not used; Address1: Not used; Address2: Not used; Address3: Not used; Address4: Not used; DocumentNumber: 3; Revision: Not used; SheetNumber: 3; SheetTotal: 16
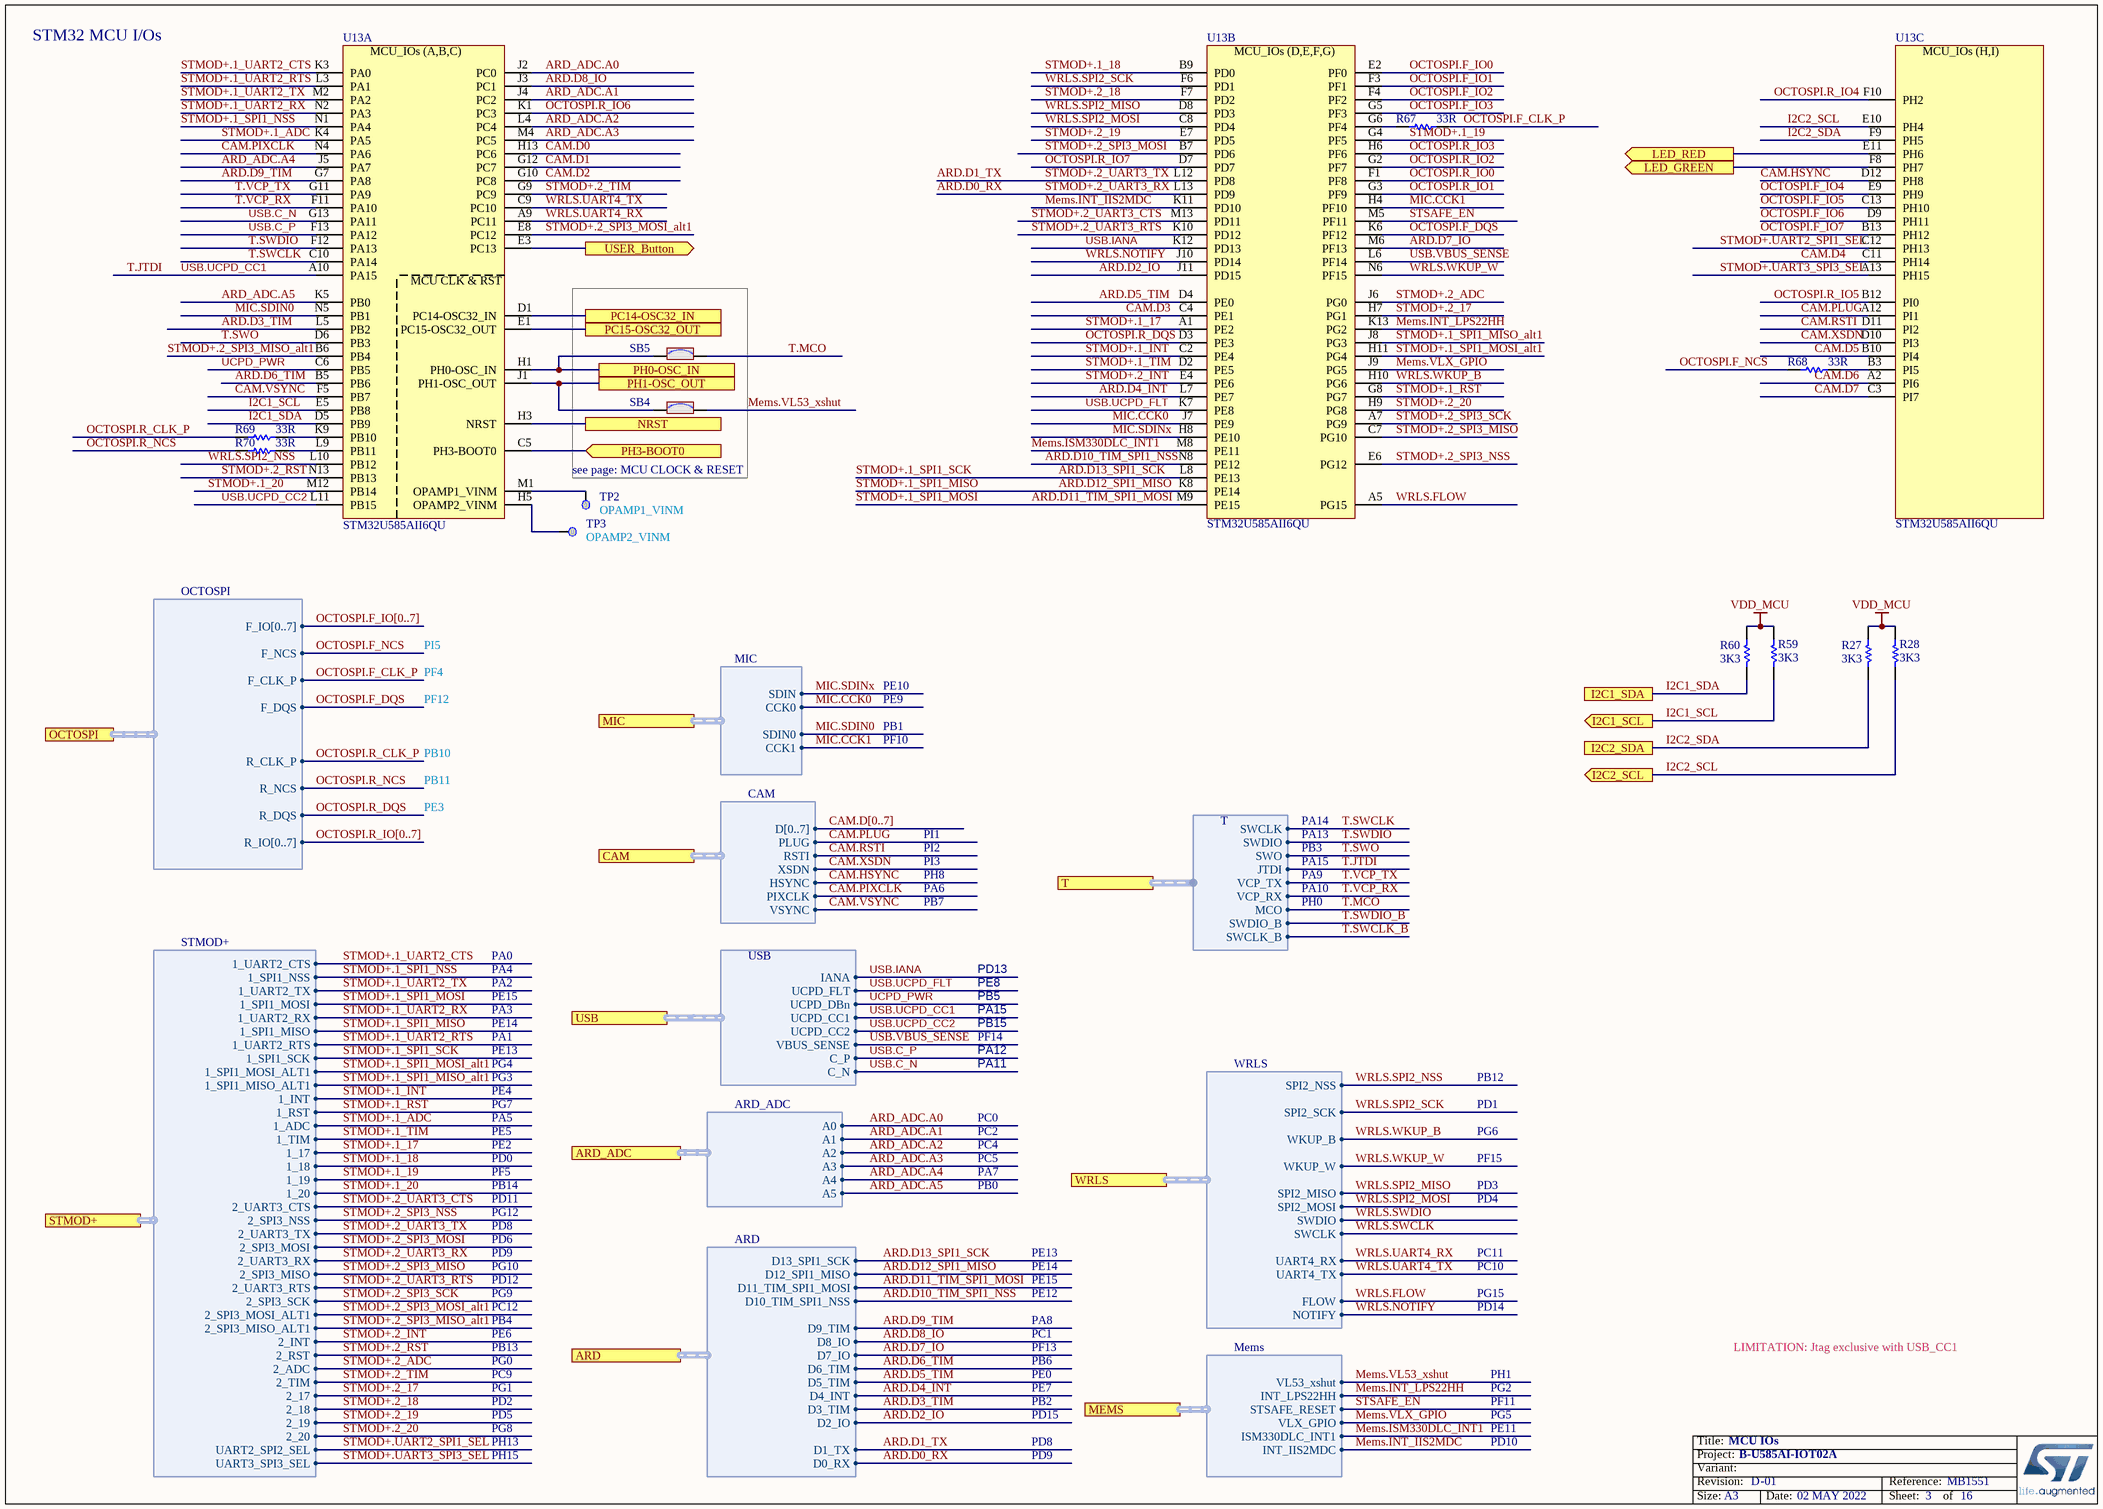
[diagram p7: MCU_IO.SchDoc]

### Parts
R27  value 3K3  [R0603]  (hidden comment: Resistor)
R28  value 3K3  [R0603]  (hidden comment: Resistor)
R59  value 3K3  [R0603]  (hidden comment: Resistor)
R60  value 3K3  [R0603]  (hidden comment: Resistor)
R67  value 33R  [R0402]  (hidden comment: Resistor)
R68  value 33R  [R0402]  (hidden comment: Resistor)
R69  value 33R  [R0402]  (hidden comment: Resistor)
R70  value 33R  [R0402]  (hidden comment: Resistor)
SB4  (no value)  [SOLDER-BRIDGE_R0603-0R]
SB5  (no value)  [SOLDER-BRIDGE_R0603-0R]
TP2  value OPAMP1_VINM  [TP_SMD_1MM]  (no BOM)
TP3  value OPAMP2_VINM  [TP_SMD_1MM]  (no BOM)
U13  STM32U585AII6QU  [ICC_UFBGA169_7X7_P050]  (parts A,B,C of 4)

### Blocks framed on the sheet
see page: MCU CLOCK & RESET: SB4 SB5

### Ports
ARD (harness ARD), ARD_ADC (harness ARD_ADC), CAM (harness CAM), I2C1_SCL (out), I2C1_SDA, I2C2_SCL (out), I2C2_SDA, LED_GREEN (out), LED_RED (out), MEMS (harness Mems), MIC (harness MIC), NRST, OCTOSPI (harness OCTOSPI), PC14-OSC32_IN, PC15-OSC32_OUT, PH0-OSC_IN, PH1-OSC_OUT, PH3-BOOT0 (in), STMOD+ (harness STMOD+), T (harness T), USB (harness USB), USER_Button (out), WRLS (harness WRLS)

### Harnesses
OCTOSPI: F_DQS, F_CLK_P, F_NCS, R_CLK_P, R_NCS, R_DQS, R_IO[0..7], F_IO[0..7]
STMOD+: 1_UART2_CTS, 1_SPI1_NSS, 1_UART2_TX, 1_SPI1_MOSI, 1_SPI1_MISO, 1_UART2_RTS, 1_ADC, 1_17, 1_18, 1_19, 1_20, 2_UART3_CTS, 2_SPI3_NSS, 2_UART3_TX, 2_SPI3_MOSI, 2_SPI3_MISO, 2_UART3_RTS, 2_UART3_RX, 1_UART2_RX, 1_SPI1_MOSI_ALT1, 2_SPI3_SCK, 2_SPI3_MOSI_ALT1, 1_SPI1_MISO_ALT1, 1_SPI1_SCK, 1_RST, 1_INT, 1_TIM, 2_SPI3_MISO_ALT1, 2_INT, 2_RST, 2_ADC, 2_TIM, 2_17, 2_18, 2_19, 2_20, UART2_SPI2_SEL, UART3_SPI3_SEL
ARD_ADC: A0, A1, A2, A3, A4, A5
ARD: D0_RX, D1_TX, D2_IO, D3_TIM, D4_INT, D5_TIM, D6_TIM, D7_IO, D8_IO, D9_TIM, D10_TIM_SPI1_NSS, D11_TIM_SPI1_MOSI, D12_SPI1_MISO, D13_SPI1_SCK
CAM: D[0..7], PLUG, XSDN, HSYNC, PIXCLK, VSYNC, RSTI
MIC: SDIN, CCK0, SDIN0, CCK1
WRLS: WKUP_B, WKUP_W, SPI2_NSS, SPI2_SCK, SPI2_MISO, SPI2_MOSI, SWDIO, SWCLK, UART4_RX, UART4_TX, FLOW, NOTIFY
USB: UCPD_FLT, UCPD_DBn, UCPD_CC2, VBUS_SENSE, C_P, C_N, UCPD_CC1, IANA
Mems: INT_LPS22HH, VLX_GPIO, ISM330DLC_INT1, INT_IIS2MDC, STSAFE_RESET, VL53_xshut
T: SWCLK, SWDIO, SWO, JTDI, VCP_RX, VCP_TX, MCO, SWDIO_B, SWCLK_B

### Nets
VDD_MCU: R27.1 R28.1 R59.1 R60.1
ARD.D0_RX: U13.L13(PD9) ; port STMOD+.2_UART3_RX, port ARD.D0_RX  [also labelled STMOD+.2_UART3_RX]
ARD.D1_TX: U13.L12(PD8) ; port STMOD+.2_UART3_TX, port ARD.D1_TX  [also labelled STMOD+.2_UART3_TX]
ARD.D2_IO: U13.J11(PD15) ; port ARD.D2_IO
ARD.D3_TIM: U13.L5(PB2) ; port ARD.D3_TIM
ARD.D4_INT: U13.L7(PE7) ; port ARD.D4_INT
ARD.D5_TIM: U13.D4(PE0) ; port ARD.D5_TIM
ARD.D6_TIM: U13.B5(PB6) ; port ARD.D6_TIM
ARD.D7_IO: U13.M6(PF13) ; port ARD.D7_IO
ARD.D8_IO: U13.J3(PC1) ; port ARD.D8_IO
ARD.D9_TIM: U13.G7(PA8) ; port ARD.D9_TIM
ARD.D10_TIM_SPI1_NSS: U13.N8(PE12) ; port ARD.D10_TIM_SPI1_NSS
ARD.D11_TIM_SPI1_MOSI: U13.M9(PE15) ; port STMOD+.1_SPI1_MOSI, port ARD.D11_TIM_SPI1_MOSI  [also labelled STMOD+.1_SPI1_MOSI]
ARD.D12_SPI1_MISO: U13.K8(PE14) ; port STMOD+.1_SPI1_MISO, port ARD.D12_SPI1_MISO  [also labelled STMOD+.1_SPI1_MISO]
ARD.D13_SPI1_SCK: U13.L8(PE13) ; port STMOD+.1_SPI1_SCK, port ARD.D13_SPI1_SCK  [also labelled STMOD+.1_SPI1_SCK]
ARD_ADC.A0: U13.J2(PC0) ; port ARD_ADC.A0
ARD_ADC.A1: U13.J4(PC2) ; port ARD_ADC.A1
ARD_ADC.A2: U13.L4(PC4) ; port ARD_ADC.A2
ARD_ADC.A3: U13.M4(PC5) ; port ARD_ADC.A3
ARD_ADC.A4: U13.J5(PA7) ; port ARD_ADC.A4
ARD_ADC.A5: U13.K5(PB0) ; port ARD_ADC.A5
CAM.D0: U13.H13(PC6)
CAM.D1: U13.G12(PC7)
CAM.D2: U13.G10(PC8)
CAM.D3: U13.C4(PE1)
CAM.D4: U13.C11(PH14)
CAM.D5: U13.B10(PI4)
CAM.D6: U13.A2(PI6)
CAM.D7: U13.C3(PI7)
CAM.HSYNC: U13.D12(PH8) ; port CAM.HSYNC
CAM.PIXCLK: U13.N4(PA6) ; port CAM.PIXCLK
CAM.PLUG: U13.A12(PI1) ; port CAM.PLUG
CAM.RSTI: U13.D11(PI2) ; port CAM.RSTI
CAM.VSYNC: U13.F5(PB7) ; port CAM.VSYNC
CAM.XSDN: U13.D10(PI3) ; port CAM.XSDN
I2C1_SCL: R59.2 U13.E5(PB8) ; port I2C1_SCL
I2C1_SDA: R60.2 U13.D5(PB9) ; port I2C1_SDA
I2C2_SCL: R28.2 U13.E10(PH4) ; port I2C2_SCL
I2C2_SDA: R27.2 U13.F9(PH5) ; port I2C2_SDA
LED_GREEN: U13.F8(PH7) ; port LED_GREEN
LED_RED: U13.E11(PH6) ; port LED_RED
Mems.INT_IIS2MDC: U13.K11(PD10) ; port MEMS.INT_IIS2MDC
Mems.INT_LPS22HH: U13.K13(PG2) ; port MEMS.INT_LPS22HH
Mems.ISM330DLC_INT1: U13.M8(PE11) ; port MEMS.ISM330DLC_INT1
Mems.VL53_xshut: SB4.2 ; port MEMS.VL53_xshut
Mems.VLX_GPIO: U13.J9(PG5) ; port MEMS.VLX_GPIO
MIC.CCK0: U13.J7(PE9) ; port MIC.CCK0
MIC.CCK1: U13.H4(PF10) ; port MIC.CCK1
MIC.SDIN0: U13.N5(PB1) ; port MIC.SDIN0
MIC.SDINx: U13.H8(PE10) ; port MIC.SDIN
NRST: U13.H3(NRST) ; port NRST
OCTOSPI.F_CLK_P: R67.2 ; port OCTOSPI.F_CLK_P
OCTOSPI.F_DQS: U13.K6(PF12) ; port OCTOSPI.F_DQS
OCTOSPI.F_IO0: U13.E2(PF0)
OCTOSPI.F_IO1: U13.F3(PF1)
OCTOSPI.F_IO2: U13.F4(PF2)
OCTOSPI.F_IO3: U13.G5(PF3)
OCTOSPI.F_IO4: U13.E9(PH9)
OCTOSPI.F_IO5: U13.C13(PH10)
OCTOSPI.F_IO6: U13.D9(PH11)
OCTOSPI.F_IO7: U13.B13(PH12)
OCTOSPI.F_NCS: R68.1 ; port OCTOSPI.F_NCS
OCTOSPI.R_CLK_P: R69.1 ; port OCTOSPI.R_CLK_P
OCTOSPI.R_DQS: U13.D3(PE3) ; port OCTOSPI.R_DQS
OCTOSPI.R_IO0: U13.F1(PF8)
OCTOSPI.R_IO1: U13.G3(PF9)
OCTOSPI.R_IO2: U13.G2(PF7)
OCTOSPI.R_IO3: U13.H6(PF6)
OCTOSPI.R_IO4: U13.F10(PH2)
OCTOSPI.R_IO5: U13.B12(PI0)
OCTOSPI.R_IO6: U13.K1(PC3)
OCTOSPI.R_IO7: U13.D7(PD7)
OCTOSPI.R_NCS: R70.1 ; port OCTOSPI.R_NCS
PC14-OSC32_IN: U13.D1(PC14-OSC32_IN) ; port PC14-OSC32_IN
PC15-OSC32_OUT: U13.E1(PC15-OSC32_OUT) ; port PC15-OSC32_OUT
PH0-OSC_IN: SB5.1 U13.H1(PH0-OSC_IN) ; port PH0-OSC_IN
PH1-OSC_OUT: SB4.1 U13.J1(PH1-OSC_OUT) ; port PH1-OSC_OUT
PH3-BOOT0: U13.C5(PH3-BOOT0) ; port PH3-BOOT0
STMOD+.1_17: U13.A1(PE2) ; port STMOD+.1_17
STMOD+.1_18: U13.B9(PD0) ; port STMOD+.1_18
STMOD+.1_19: U13.G4(PF5) ; port STMOD+.1_19
STMOD+.1_20: U13.M12(PB14) ; port STMOD+.1_20
STMOD+.1_ADC: U13.K4(PA5) ; port STMOD+.1_ADC
STMOD+.1_INT: U13.C2(PE4) ; port STMOD+.1_INT
STMOD+.1_RST: U13.G8(PG7) ; port STMOD+.1_RST
STMOD+.1_SPI1_MISO_alt1: U13.J8(PG3) ; port STMOD+.1_SPI1_MISO_ALT1
STMOD+.1_SPI1_MOSI_alt1: U13.H11(PG4) ; port STMOD+.1_SPI1_MOSI_ALT1
STMOD+.1_SPI1_NSS: U13.N1(PA4) ; port STMOD+.1_SPI1_NSS
STMOD+.1_TIM: U13.D2(PE5) ; port STMOD+.1_TIM
STMOD+.1_UART2_CTS: U13.K3(PA0) ; port STMOD+.1_UART2_CTS
STMOD+.1_UART2_RTS: U13.L3(PA1) ; port STMOD+.1_UART2_RTS
STMOD+.1_UART2_RX: U13.N2(PA3) ; port STMOD+.1_UART2_RX
STMOD+.1_UART2_TX: U13.M2(PA2) ; port STMOD+.1_UART2_TX
STMOD+.2_17: U13.H7(PG1) ; port STMOD+.2_17
STMOD+.2_18: U13.F7(PD2) ; port STMOD+.2_18
STMOD+.2_19: U13.E7(PD5) ; port STMOD+.2_19
STMOD+.2_20: U13.H9(PG8) ; port STMOD+.2_20
STMOD+.2_ADC: U13.J6(PG0) ; port STMOD+.2_ADC
STMOD+.2_INT: U13.E4(PE6) ; port STMOD+.2_INT
STMOD+.2_RST: U13.N13(PB13) ; port STMOD+.2_RST
STMOD+.2_SPI3_MISO: U13.C7(PG10) ; port STMOD+.2_SPI3_MISO
STMOD+.2_SPI3_MISO_alt1: U13.B6(PB4) ; port STMOD+.2_SPI3_MISO_ALT1
STMOD+.2_SPI3_MOSI: U13.B7(PD6) ; port STMOD+.2_SPI3_MOSI
STMOD+.2_SPI3_MOSI_alt1: U13.E8(PC12) ; port STMOD+.2_SPI3_MOSI_ALT1
STMOD+.2_SPI3_NSS: U13.E6(PG12) ; port STMOD+.2_SPI3_NSS
STMOD+.2_SPI3_SCK: U13.A7(PG9) ; port STMOD+.2_SPI3_SCK
STMOD+.2_TIM: U13.G9(PC9) ; port STMOD+.2_TIM
STMOD+.2_UART3_CTS: U13.M13(PD11) ; port STMOD+.2_UART3_CTS
STMOD+.2_UART3_RTS: U13.K10(PD12) ; port STMOD+.2_UART3_RTS
STMOD+.UART2_SPI1_SEL: U13.C12(PH13) ; port STMOD+.UART2_SPI2_SEL
STMOD+.UART3_SPI3_SEL: U13.A13(PH15) ; port STMOD+.UART3_SPI3_SEL
STSAFE_EN: U13.M5(PF11) ; port MEMS.STSAFE_RESET
T.JTDI: U13.A10(PA15) ; port USB.UCPD_CC1, port T.JTDI  [also labelled USB.UCPD_CC1]
T.MCO: SB5.2 ; port T.MCO
T.SWCLK: U13.C10(PA14) ; port T.SWCLK
T.SWDIO: U13.F12(PA13) ; port T.SWDIO
T.SWO: U13.D6(PB3) ; port T.SWO
T.VCP_RX: U13.F11(PA10) ; port T.VCP_RX
T.VCP_TX: U13.G11(PA9) ; port T.VCP_TX
UCPD_PWR: U13.C6(PB5) ; port USB.UCPD_DBn
USB.C_N: U13.G13(PA11) ; port USB.C_N
USB.C_P: U13.F13(PA12) ; port USB.C_P
USB.IANA: U13.K12(PD13) ; port USB.IANA
USB.UCPD_CC2: U13.L11(PB15) ; port USB.UCPD_CC2
USB.UCPD_FLT: U13.K7(PE8) ; port USB.UCPD_FLT
USB.VBUS_SENSE: U13.L6(PF14) ; port USB.VBUS_SENSE
USER_BUTTON: U13.E3(PC13) ; port USER_Button
WRLS.FLOW: U13.A5(PG15) ; port WRLS.FLOW
WRLS.NOTIFY: U13.J10(PD14) ; port WRLS.NOTIFY
WRLS.SPI2_MISO: U13.D8(PD3) ; port WRLS.SPI2_MISO
WRLS.SPI2_MOSI: U13.C8(PD4) ; port WRLS.SPI2_MOSI
WRLS.SPI2_NSS: U13.L10(PB12) ; port WRLS.SPI2_NSS
WRLS.SPI2_SCK: U13.F6(PD1) ; port WRLS.SPI2_SCK
WRLS.UART4_RX: U13.A9(PC11) ; port WRLS.UART4_RX
WRLS.UART4_TX: U13.C9(PC10) ; port WRLS.UART4_TX
WRLS.WKUP_B: U13.H10(PG6) ; port WRLS.WKUP_B
WRLS.WKUP_W: U13.N6(PF15) ; port WRLS.WKUP_W
NetR67_1: R67.1 U13.G6(PF4)
NetR68_2: R68.2 U13.B3(PI5)
NetR69_2: R69.2 U13.K9(PB10)
NetR70_2: R70.2 U13.L9(PB11)
NetTP2_1: TP2.1 U13.M1(OPAMP1_VINM)
NetTP3_1: TP3.1 U13.H5(OPAMP2_VINM)

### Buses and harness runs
bus CAM.D[0..7]
bus OCTOSPI.F_IO[0..7]
bus OCTOSPI.R_IO[0..7]

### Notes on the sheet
- STM32 MCU I/Os
- PI5
- PF12
- PF4
- PE9
- PE10
- PB10
- PB11
- PB1
- PF10
- PE3
- PI1
- PI2
- PA14
- PA13
- PB3
- PI3
- PH8
- PA6
- PB7
- PA15
- PA10
- PA9
- PH0
- PA0
- PA4
- PA2
- PE8
- PD13
- PE14
- PA3
- PE15
- PA1
- PE13
- PF14
- PB15
- PB5
- PA12
- PG3
- PG4
- PE4
- PA5
- PG7
- PC0
- PA11
- PB12
- PD1
- PE5
- PE2
- PD0
- PF5
- PB14
- PC2
- PC5
- PA7
- PC4
- PB0
- PD3
- PF15
- PG6
- PD11
- PG12
- PD8
- PD9
- PD6
- PD4
- PC11
- PG10
- PD12
- PG9
- PC12
- PB4
- PA8
- PE12
- PC10
- PD14
- PG15
- PE6
- PG0
- PC9
- PB13
- PG1
- PE0
- PB6
- PE7
- PC1
- PF13
- PG2
- PH1
- LIMITATION: Jtag exclusive with USB_CC1
- PD2
- PG8
- PD5
- PH13
- PH15
- PB2
- PD15
- PE11
- PD10
- PG5
- PF11

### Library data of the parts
R27 R28 R59 R60 = MCD-00352: Resistor,3K3,0603,1%,1/10W; Manufacturer_Part_Number: RC0603FR-073K3L; Manufacturer: YAGEO; ECCN_US: EAR99; ECCN_EU: NEC; Provided_By: SUBCO
R67-R70 = MCD-00455: Resistor, 33R, 0402, +/-1%, 1/16W; Part_Preference: Recommended; Manufacturer: YAGEO; Manufacturer_Part_Number: RC0402FR-0733RL; Component_Country_Of_Origin: China; ShowFields: YES; ID: 2821
SB4 SB5 = MCD-00071: as SB10 on sheet ARDUINO
TP2 TP3 = MCD-00074: Test Point 1mm; Part_Type: Mechanical; Initial_Board_Reference: MB1274
U13 = MCD-02055: STM32U585AII6Q MCU,Low Power BGA169 7x7, pitch0.5, with encryption, Q for Int SMPS.; Part_Type: IC; Manufacturer: STMICROELECTRONICS; ECCN_US: 5A002A4; Provided_By: SUBCO

## Sheet MCU_PWR.SchDoc: MCU PWR
size A4; Date: Not used; ApprovedBy: Not used; CheckedBy: Not used; Author: Not used; CompanyName: STMicroelectronics; DrawnBy: Not used; Engineer: Not used; Organization: Not used; Address1: Not used; Address2: Not used; Address3: Not used; Address4: Not used; DocumentNumber: 5; Revision: Not used; SheetNumber: 5; SheetTotal: 16
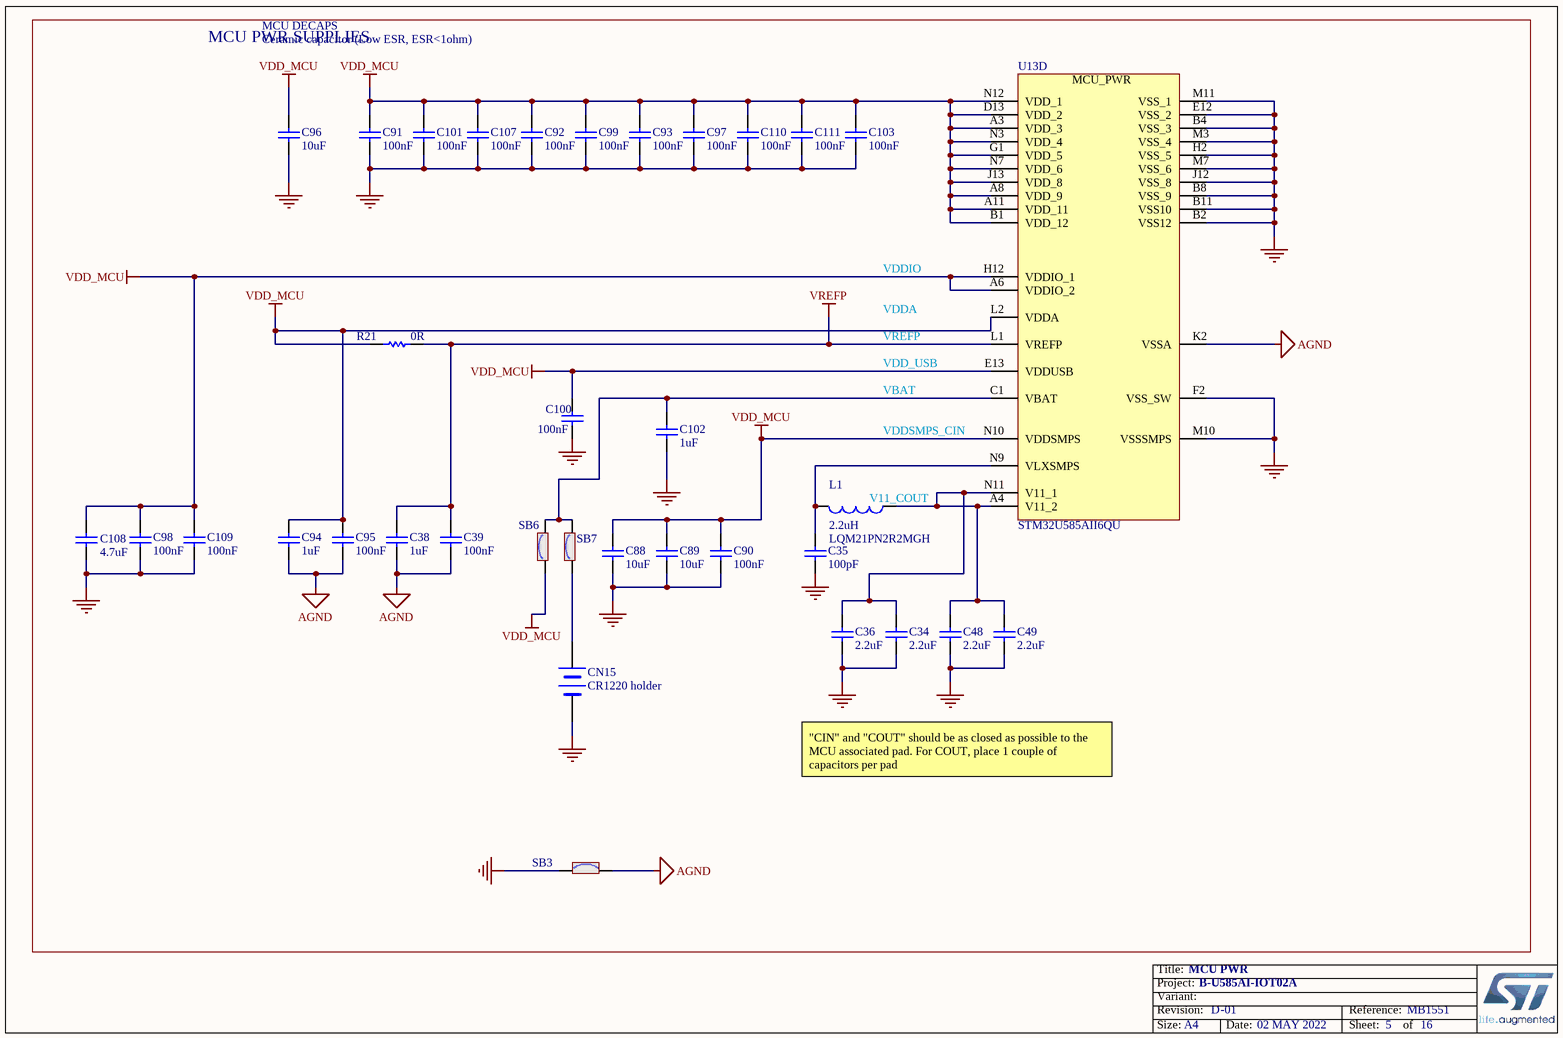
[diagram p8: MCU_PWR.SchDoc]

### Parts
C34  value 2.2uF  [C0402]
C35  value 100pF  [C0402]
C36  value 2.2uF  [C0402]
C38  value 1uF  [C0603]
C39  value 100nF  [C0402]
C48  value 2.2uF  [C0402]
C49  value 2.2uF  [C0402]
C88  value 10uF  [C0402]  (hidden comment: Capacitor)
C89  value 10uF  [C0402]  (hidden comment: Capacitor)
C90  value 100nF  [C0402]
C91  value 100nF  [C0402]
C92  value 100nF  [C0402]
C93  value 100nF  [C0402]
C94  value 1uF  [C0603]
C95  value 100nF  [C0402]
C96  value 10uF  [C0402]  (hidden comment: Capacitor)
C97  value 100nF  [C0402]
C98  value 100nF  [C0402]
C99  value 100nF  [C0402]
C100  value 100nF  [C0402]
C101  value 100nF  [C0402]
C102  value 1uF  [C0603]
C103  value 100nF  [C0402]
C107  value 100nF  [C0402]
C108  value 4.7uF  [C0603]
C109  value 100nF  [C0402]
C110  value 100nF  [C0402]
C111  value 100nF  [C0402]
CN15  value CR1220 holder  [BAT_HARWIN_S8411-45R_SMD_2P]
L1  value 2.2uH  Manufacturer_Part_Number: LQM21PN2R2MGH  [L0805_H0P9]  (hidden comment: Inductor)
R21  value 0R  [R0402]
SB3  (no value)  [SOLDER-BRIDGE_R0603-0R]
SB6  (no value)  [SOLDER-BRIDGE_R0603-0R]
SB7  (no value)  [SOLDER-BRIDGE_R0603-0R]
U13  STM32U585AII6QU  [ICC_UFBGA169_7X7_P050]  (part D of 4)

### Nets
AGND: C38.2 C39.1 C94.2 C95.1 SB3.2 U13.K2(VSSA)
GND: C34.1 C35.1 C36.1 C48.1 C49.1 C88.1 C89.1 C90.1 C91.1 C92.1 C93.1 C96.1 C97.1 C98.1 C99.1 C100.1 C101.1 C102.2 C103.1 C107.1 C108.1 C109.1 C110.1 C111.1 CN15.2(-) SB3.1 U13.B2(VSS12) U13.B4(VSS_3) U13.B8(VSS_9) U13.B11(VSS10) U13.E12(VSS_2) U13.F2(VSS_SW) U13.H2(VSS_5) U13.J12(VSS_8) U13.M3(VSS_4) U13.M7(VSS_6) U13.M10(VSSSMPS) U13.M11(VSS_1)
VDD_MCU: C88.2 C89.2 C90.2 C91.2 C92.2 C93.2 C94.1 C95.2 C96.2 C97.2 C98.2 C99.2 C100.2 C101.2 C103.2 C107.2 C108.2 C109.2 C110.2 C111.2 R21.1 SB6.1 U13.A3(VDD_3) U13.A6(VDDIO_2) U13.A8(VDD_9) U13.A11(VDD_11) U13.B1(VDD_12) U13.D13(VDD_2) U13.E13(VDDUSB) U13.G1(VDD_5) U13.H12(VDDIO_1) U13.J13(VDD_8) U13.L2(VDDA) U13.N3(VDD_4) U13.N7(VDD_6) U13.N10(VDDSMPS) U13.N12(VDD_1)
VREFP: C38.1 C39.2 R21.2 U13.L1(VREFP)
NetC34_2: C34.2 C36.2 C48.2 C49.2 L1.1 U13.A4(V11_2) U13.N11(V11_1)
NetC35_2: C35.2 L1.2 U13.N9(VLXSMPS)
NetC102_1: C102.1 SB6.2 SB7.2 U13.C1(VBAT)
NetCN15_1: CN15.1(+) SB7.1

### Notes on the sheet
- MCU PWR SUPPLIES
- MCU DECAPS
- Ceramic capacitor (Low ESR, ESR<1ohm)
- VDDA
- VDDIO
- VDD_USB
- VREFP
- VDDSMPS_CIN
- VBAT
- (near L1) V11_COUT
- "CIN" and "COUT" should be as closed as possible to the MCU associated pad. For COUT, place 1 couple of capacitors per pad

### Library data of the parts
C34 C36 C48 C49 = MCD-01823: Capacitor,MLCC,2.2uF,6V3,X5R,10%,0402,T=0.5; Manufacturer_Part_Number: GRM155R60J225KE95D; Manufacturer: MURATA; ECCN_US: EAR99; ECCN_EU: NEC; Provided_By: SUBCO
C35 = MCD-00205: Capacitor, MLCC, 100pF, 50V, NPO, 5%, 0402, T=0,5mm; Manufacturer_Part_Number: CC0402JRNPO9BN101; Manufacturer: YAGEO; Provided_By: Subcon; Initial_Board_Reference: MB1361
C38 C94 C102 = MCD-00010: as C5 on sheet AUDIO
C39 C90-C93 C95 C97-C101 C103 C107 C109-C111 = MCD-00006: as C56 on sheet BOARD_PWR
C88 C89 C96 = MCD-01355: as C115 on sheet BOARD_PWR
C108 = MCD-00009: as C54 on sheet BOARD_PWR
CN15 = MCD-00558: Battery Coin Cell holder, CR1220_12mm, Height 4.25mm; Part_Type: Connector; Manufacturer_Part_Number: S8411-45R; Manufacturer: HARWIN; Provided_By: Subcon; Initial_Board_Reference: MB1331
L1 = MCD-01060: Inductor, 2.2uH, 20%, Isat 0.7A, DCR 0.156Ohm, 0805; Manufacturer: MURATA; Part_Preference: Recommended
R21 = MCD-00052: as R47 on sheet ARDUINO
SB3 = MCD-00071: as SB9 on sheet BOARD_PWR
SB6 SB7 = MCD-00071: as SB10 on sheet ARDUINO
U13 = MCD-02055: as U13 on sheet MCU_IO

## Sheet Mechanical_Parts.SchDoc: MECHANICAL PART
size A4; Date: Not used; ApprovedBy: Not used; CheckedBy: Not used; Author: Not used; CompanyName: STMicroelectronics; DrawnBy: Not used; Engineer: Not used; Organization: Not used; Address1: Not used; Address2: Not used; Address3: Not used; Address4: Not used; DocumentNumber: 16; Revision: Not used; SheetNumber: 16; SheetTotal: 16
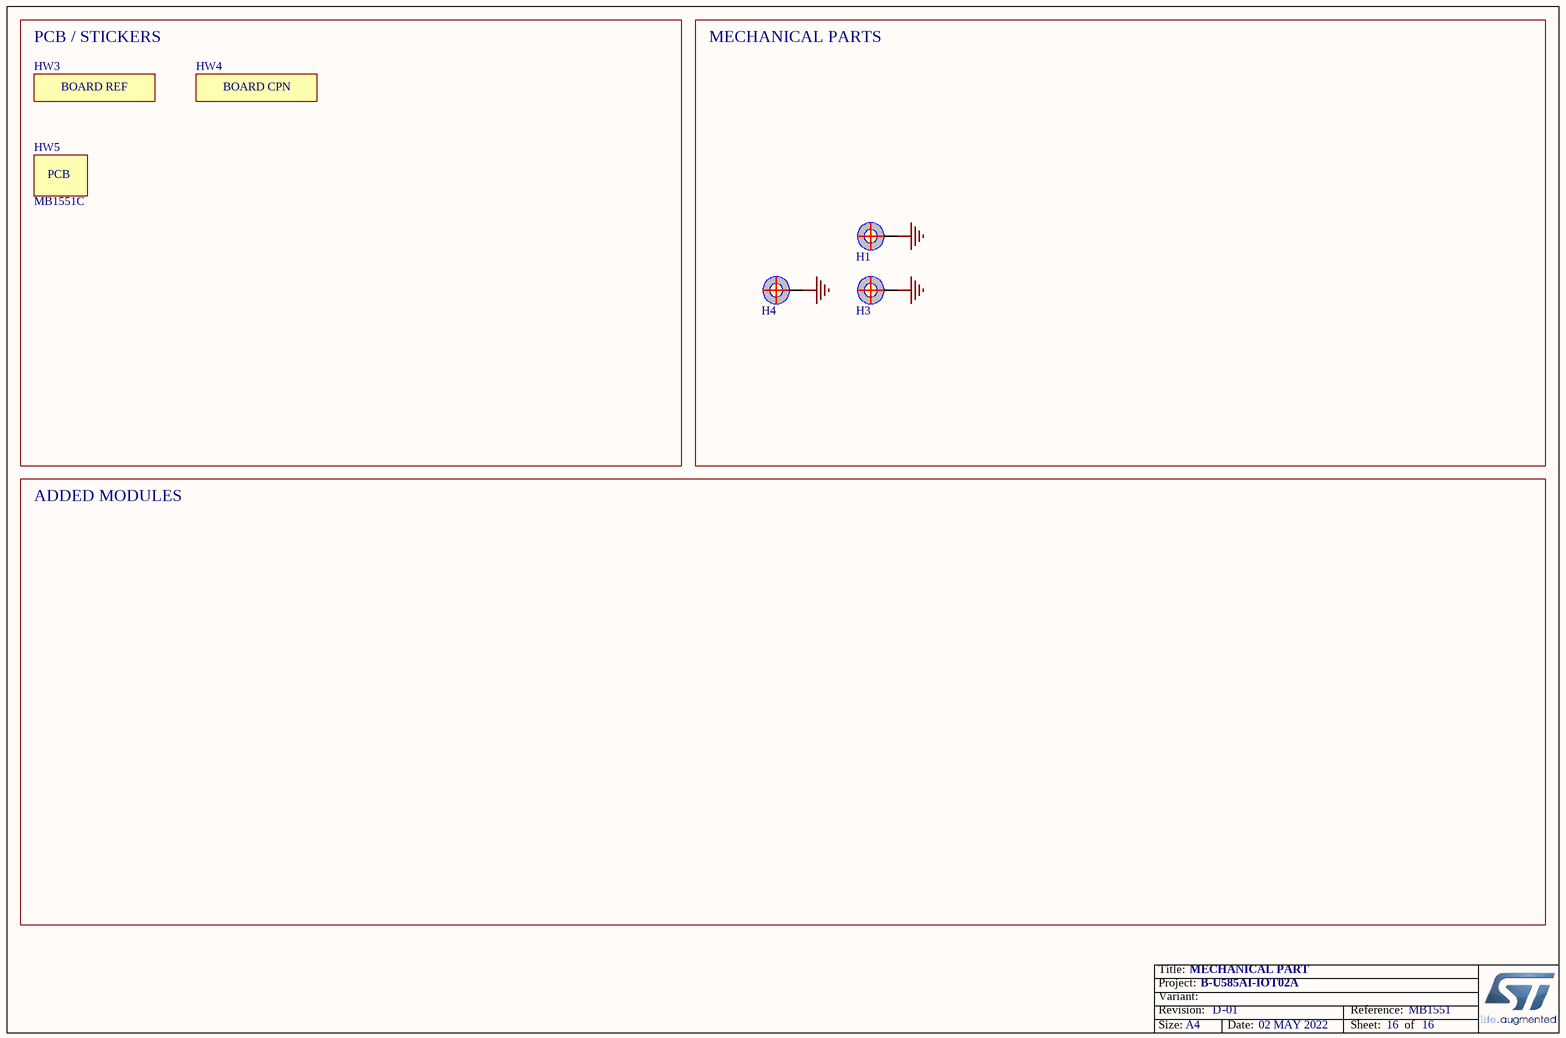
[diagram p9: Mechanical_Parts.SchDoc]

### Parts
H1  (no value)  [PTH_M1261-3005-N_3P5X6_M3_H14]  (no BOM)
H3  (no value)  [PTH_M1261-3005-N_3P5X6_M3_H14]  (no BOM)
H4  (no value)  [PTH_M1261-3005-N_3P5X6_M3_H14]  (no BOM)
HW3  (no value)  [STICKER_BOARD-REF_25X5]  (mechanical)
HW4  (no value)  [STICKER_BOARD-CPN_25X5]  (mechanical)
HW5  value MB1551C  (mechanical)

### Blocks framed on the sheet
PCB / STICKERS: HW3-HW5
MECHANICAL PARTS: H1 H3 H4

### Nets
GND: H1.1 H3.1 H4.1

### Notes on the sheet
- ADDED MODULES

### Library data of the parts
H1 H3 H4 = MCD-00035: POSITION HOLE C6D3R5; Part_Type: Mechanical; Initial_Board_Reference: MB1274
HW3 = MCD-00235: Sticker to mention board reference + serial number; Part_Type: Mechanical; Manufacturer_Part_Number: NA; Provided_By: Subcon; Initial_Board_Reference: MB1319
HW4 = MCD-00547: Sticker to mention board CPN code; Part_Type: Mechanical; Manufacturer_Part_Number: NA; Provided_By: Subcon; Initial_Board_Reference: MB1319; Remark: PCH W35 footprint requested to have a space on board for stickers.
HW5 = MCD-00216: PCB, xxxx for PCB ref, Y for revision; Part_Type: Mechanical; Provided_By: Subcon; Initial_Board_Reference: MB1319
